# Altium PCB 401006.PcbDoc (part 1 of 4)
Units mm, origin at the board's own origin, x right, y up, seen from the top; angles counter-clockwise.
Board outline 117 x 63.5 mm, 4 copper layers (Top Layer, Mid-Layer 1, Mid-Layer 2, Bottom Layer), stack 1.68 mm thick; 205 components, 151 nets, 838 pads, 1570 vias.
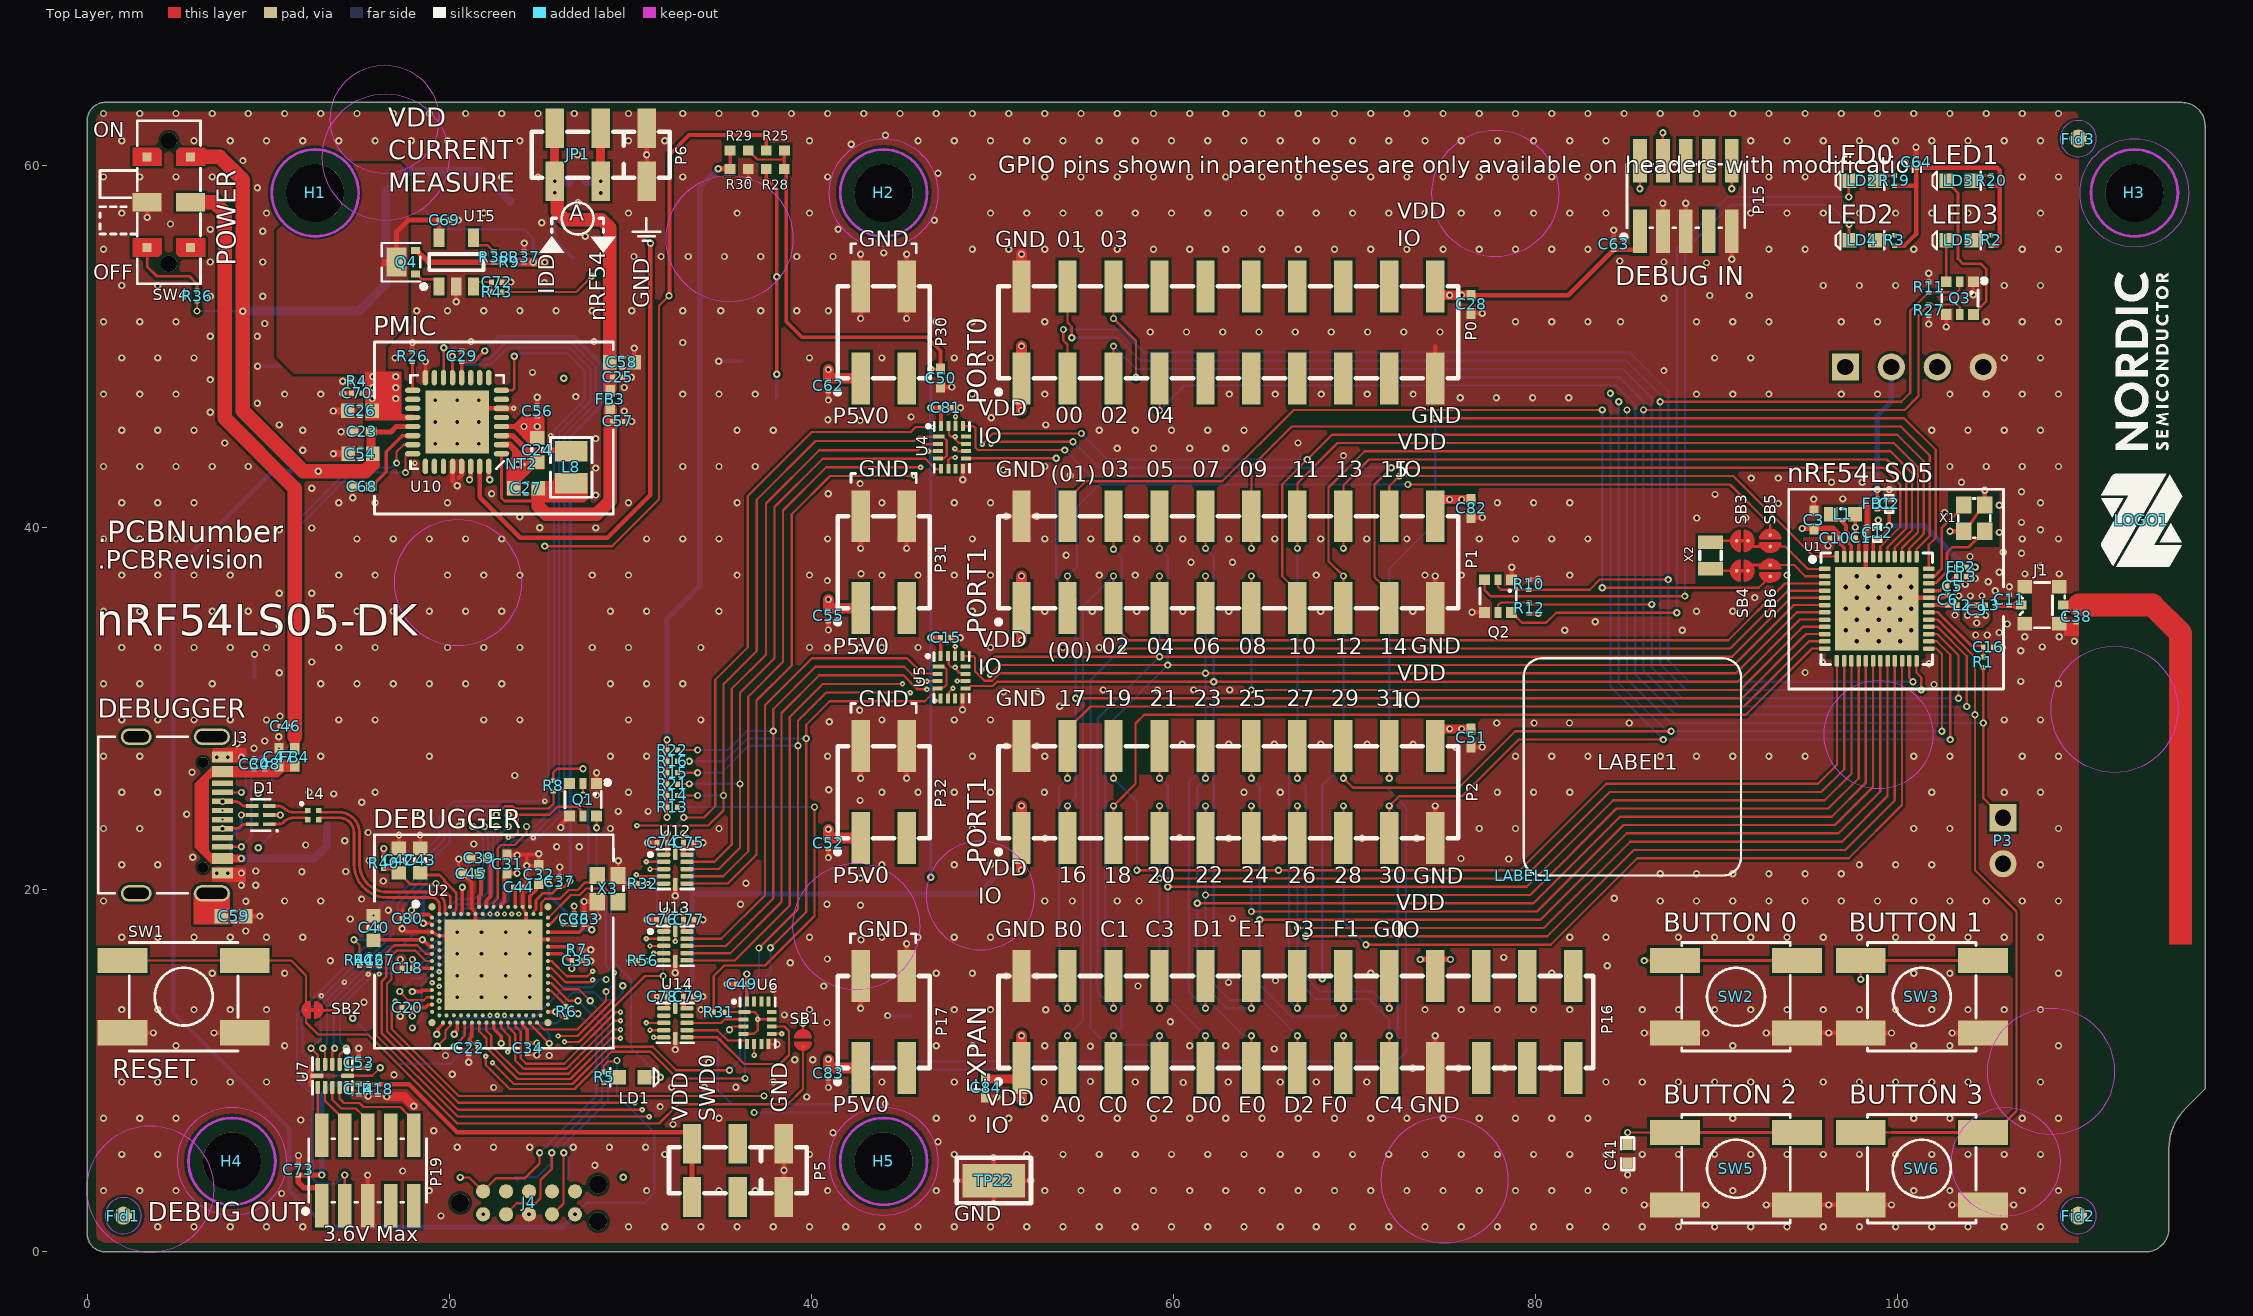
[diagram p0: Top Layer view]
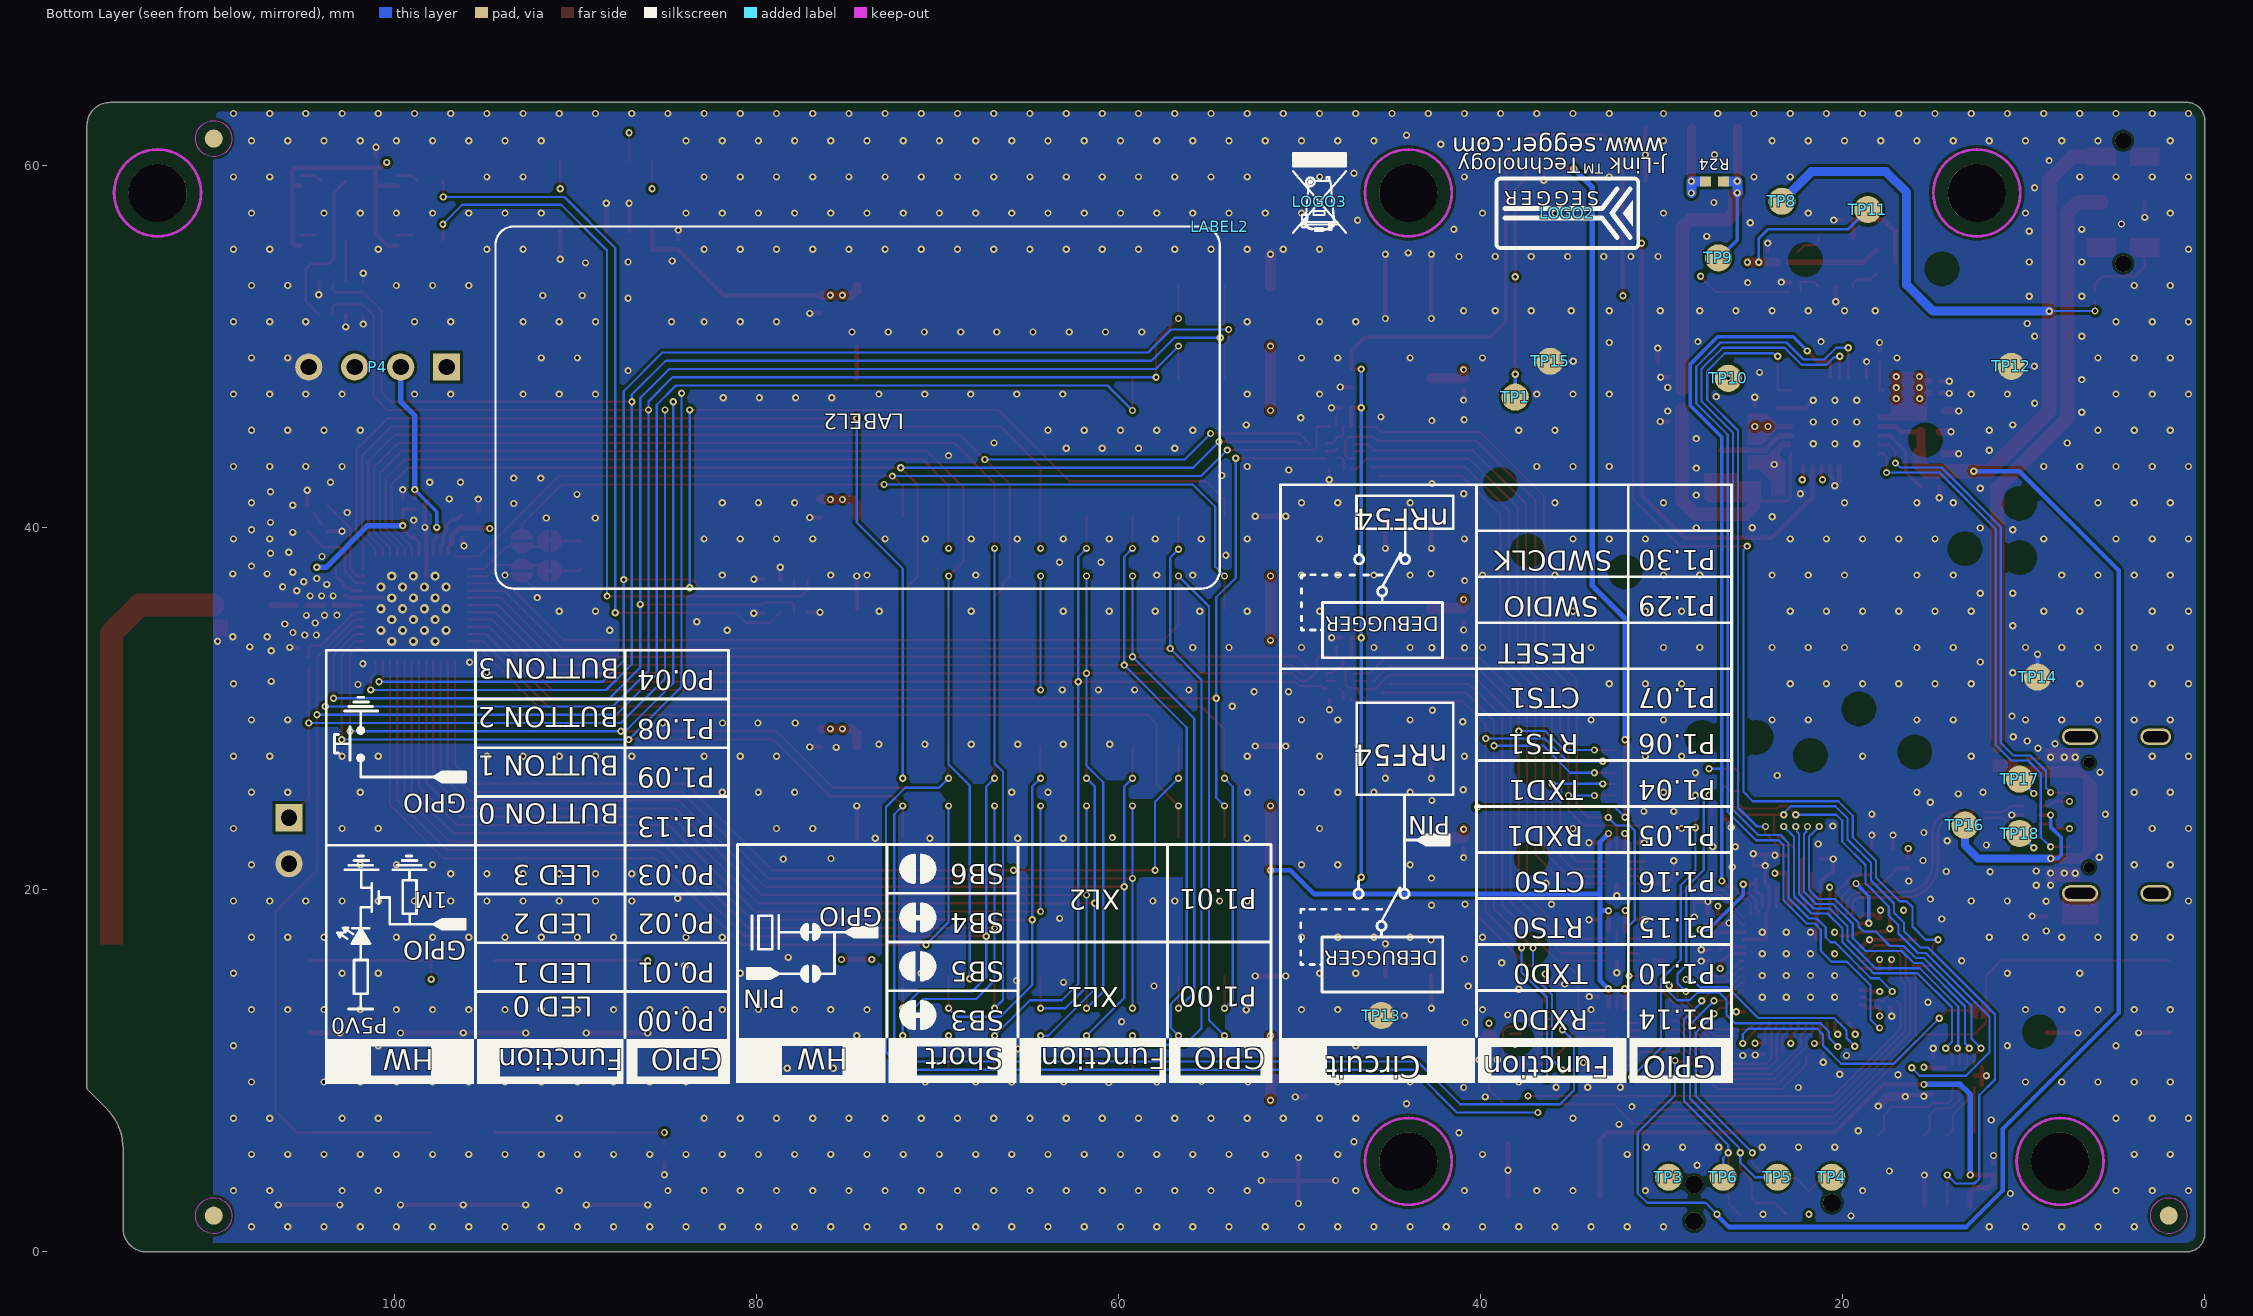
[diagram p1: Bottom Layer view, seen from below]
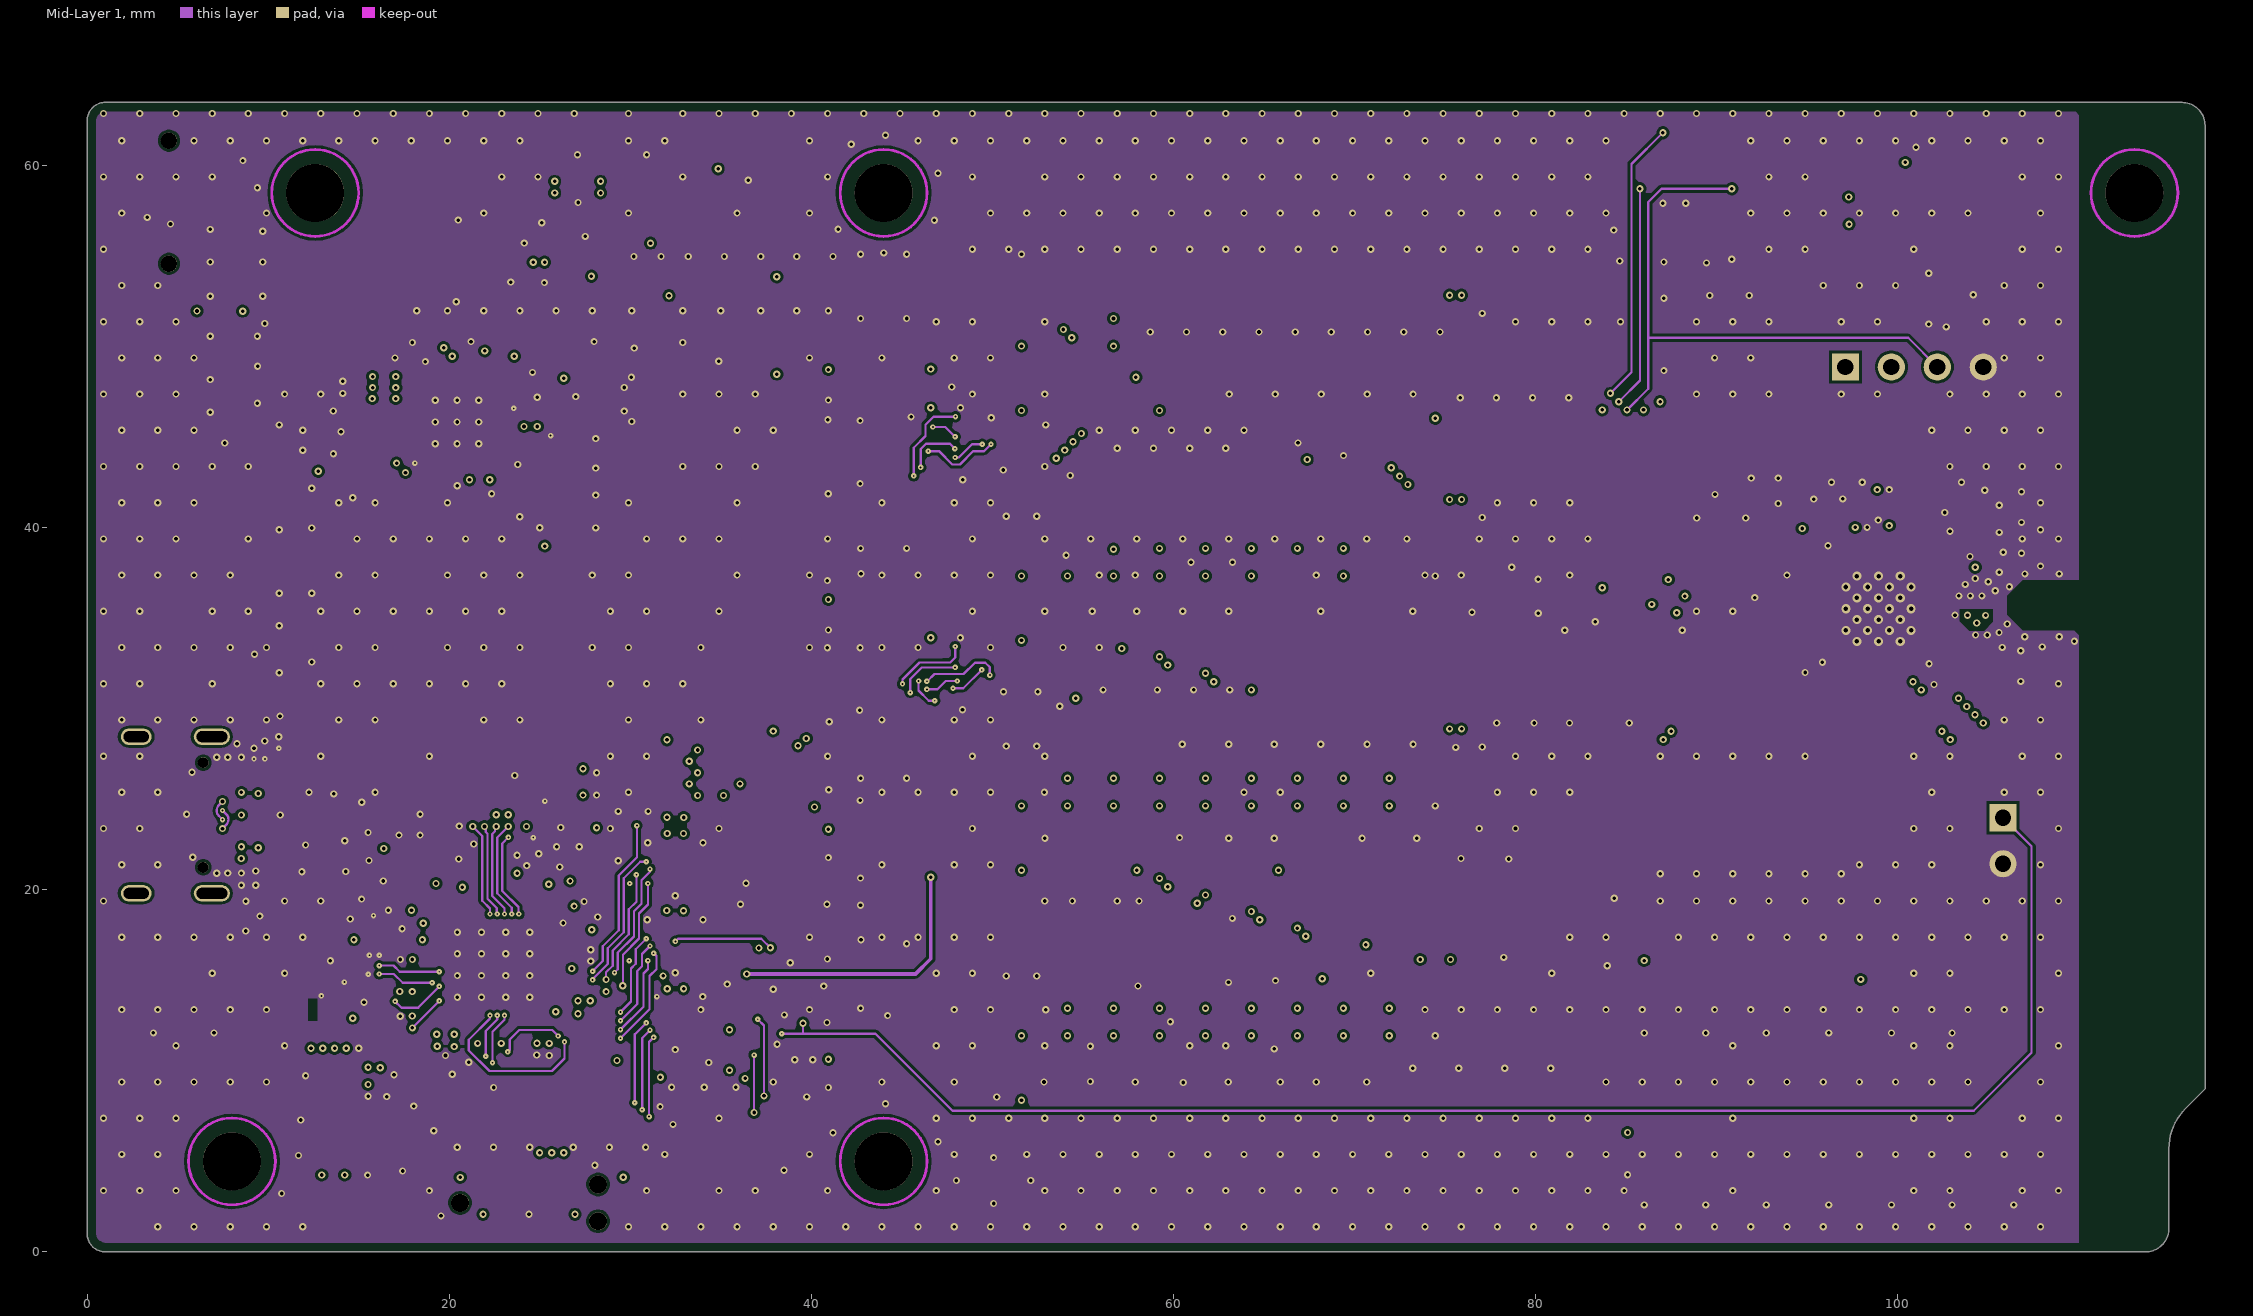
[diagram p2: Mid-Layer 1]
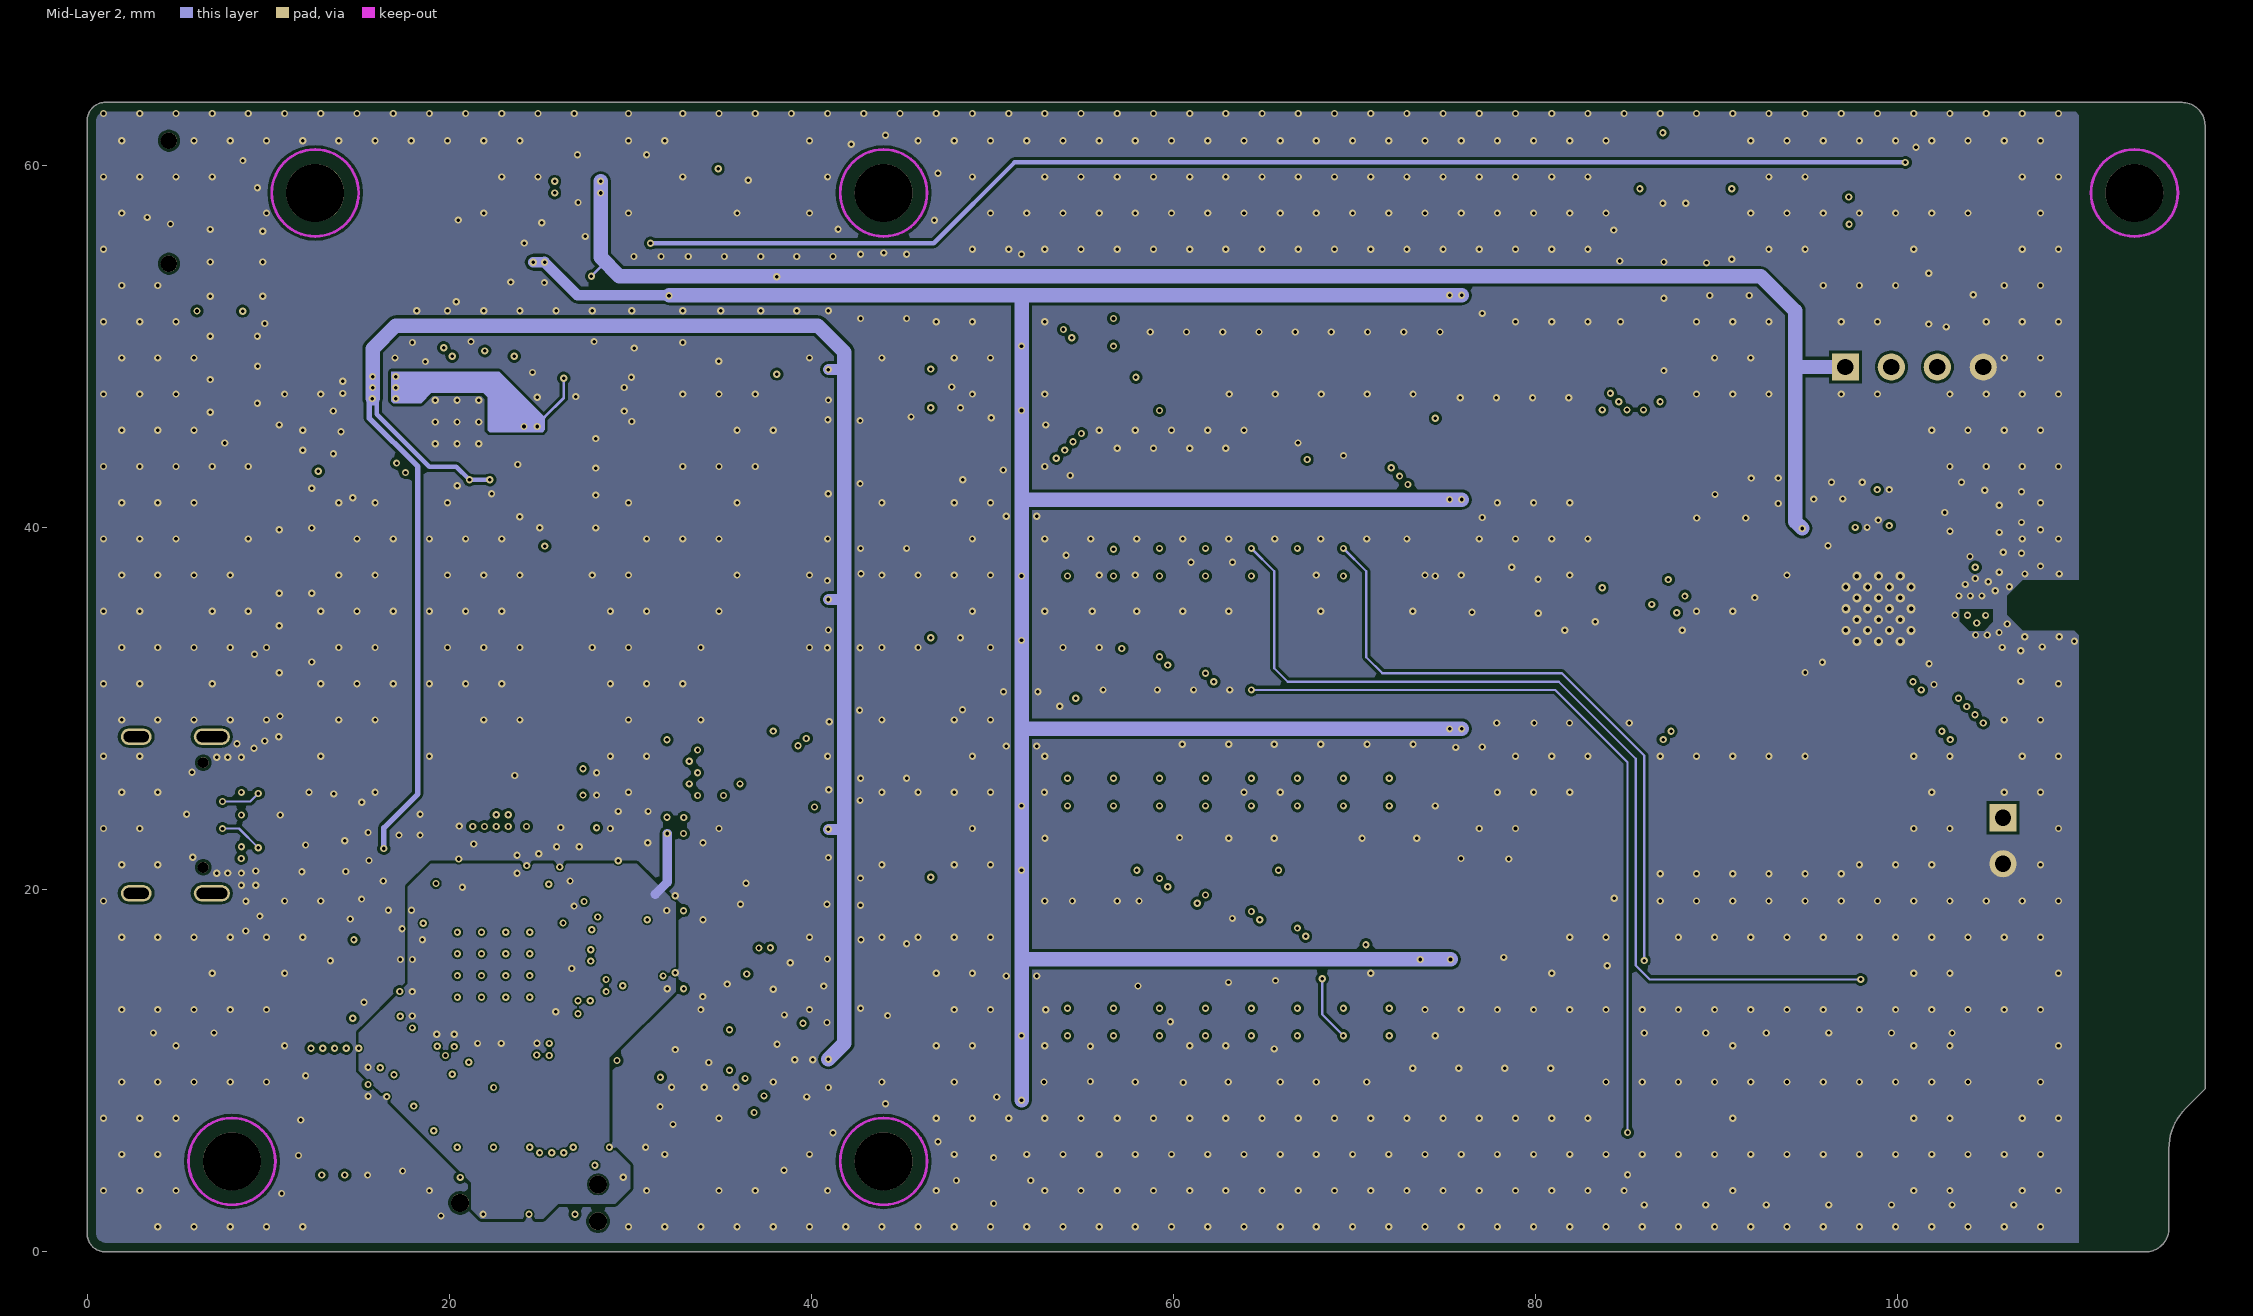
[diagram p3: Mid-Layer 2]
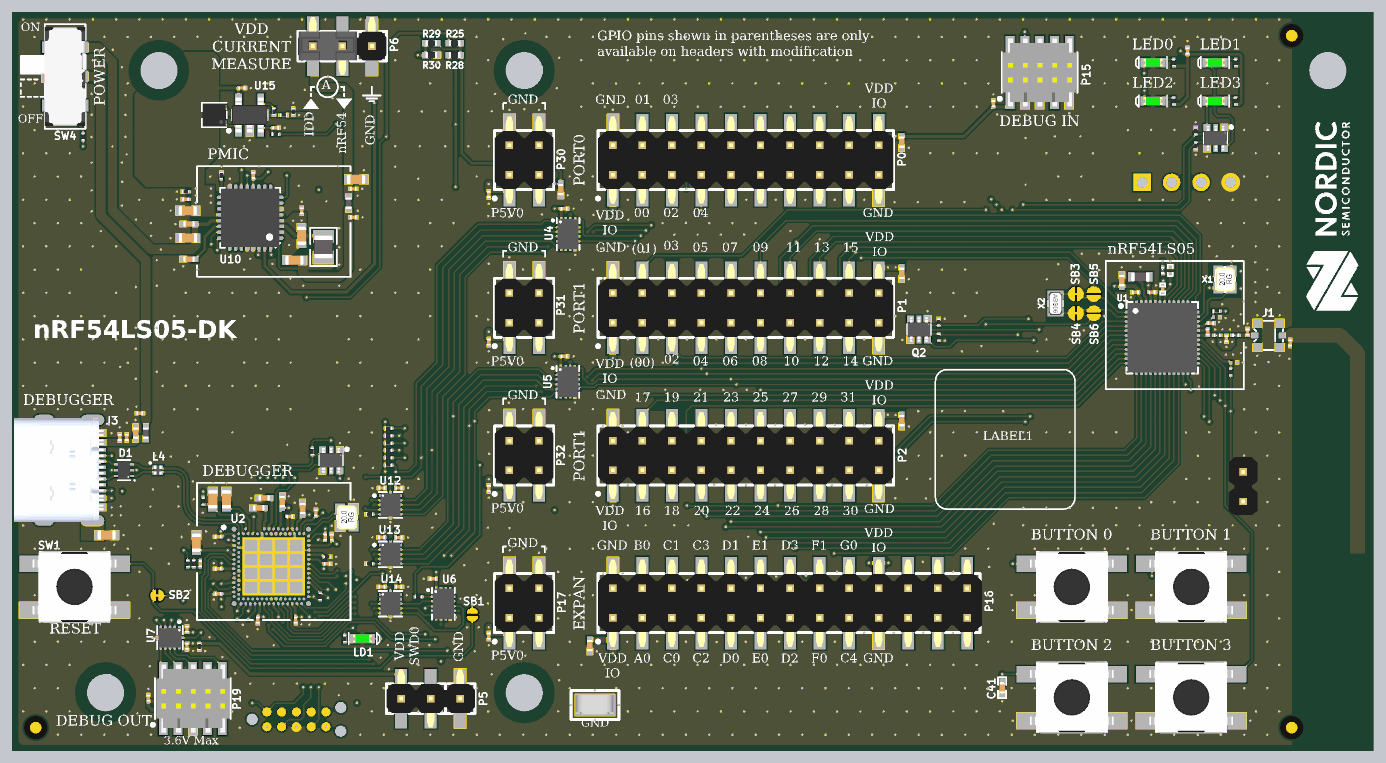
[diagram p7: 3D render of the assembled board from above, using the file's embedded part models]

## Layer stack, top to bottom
Top Solder: solder mask 0.0254, SM-003, Dk 4
Top Layer: signal copper 0.035
Dielectric 1: prepreg 0.07, PP-021, Dk 4.2
Mid-Layer 1: signal copper 0.035
Dielectric 2: core 1.4, Core-042, Dk 4.2
Mid-Layer 2: signal copper 0.035
Dielectric 3: prepreg 0.07, PP-021, Dk 4.2
Bottom Layer: signal copper 0.035
Bottom Solder: solder mask 0.0254, SM-003, Dk 4

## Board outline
1.016,0 cw(c1.016,1.016) 0,1.016 0,62.484 cw(c1.016,62.484) 1.016,63.5 115.734,63.5 cw(c115.734,62.23) 117.004,62.23 117.004,9 115.92,7.916 ccw(c118.132,5.705) 115.004,5.705 115.004,1.295 cw(c113.709,1.295) 113.709,0

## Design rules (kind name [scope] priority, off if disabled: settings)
AssemblyTestPointUsage [All] p1 off:
AssemblyTestpoint [All] p1 off: testpointundercomponent=TRUE minsize=1.016 maxsize=2.54 preferedsize=1.524 minholesize=0 maxholesize=1.016 preferedholesize=0.813 testpointgrid=0.025 usegrid=TRUE gridtolerance=0 allowsidetop=TRUE allowsidebottom=TRUE
BoardOutlineClearance [All] p1: gap=0.508 ignorepadtopadclearanceinfootprint=FALSE except(0: Arc-SplitContinuation Track-SplitContinuation SMDPad-SplitContinuation THPad-SplitContinuation Via-SplitContinuation Fill-SplitContinuation Poly-SplitContinuation Region-SplitContinuation Text-SplitContinuation)
Clearance "Schematic Clearance Constraint_4" [InComponent('H3')] p1: gap=0.254 ignorepadtopadclearanceinfootprint=TRUE except(0: Arc-Hole Track-Hole SMDPad-Hole THPad-Hole Via-Hole Fill-Hole Poly-Hole Region-Hole Text-Hole)
Clearance "Schematic Clearance Constraint_3" [InComponent('H4')] p2: gap=0.254 ignorepadtopadclearanceinfootprint=TRUE except(0: Arc-Hole Track-Hole SMDPad-Hole THPad-Hole Via-Hole Fill-Hole Poly-Hole Region-Hole Text-Hole)
Clearance "Schematic Clearance Constraint_2" [InComponent('H2')] p3: gap=0.254 ignorepadtopadclearanceinfootprint=TRUE except(0: Arc-Hole Track-Hole SMDPad-Hole THPad-Hole Via-Hole Fill-Hole Poly-Hole Region-Hole Text-Hole)
Clearance "Schematic Clearance Constraint_1" [InComponent('H5')] p4: gap=0.254 ignorepadtopadclearanceinfootprint=TRUE except(0: Arc-Hole Track-Hole SMDPad-Hole THPad-Hole Via-Hole Fill-Hole Poly-Hole Region-Hole Text-Hole)
Clearance "Schematic Clearance Constraint" [InComponent('H1')] p5: gap=0.254 ignorepadtopadclearanceinfootprint=TRUE except(0: Arc-Hole Track-Hole SMDPad-Hole THPad-Hole Via-Hole Fill-Hole Poly-Hole Region-Hole Text-Hole)
Clearance ANT_Clearance [InNet('ANT') or InNet('RF') or InNet('NetC9_2') or InNet('NetC6_2')] p6: gap=0.127 ignorepadtopadclearanceinfootprint=FALSE
Clearance Polygon_Clearance [(InNamedPolygon('Mid_Layer1-GND')) or (InNamedPolygon('Bottom_Layer-GND')) or (InNamedPolygon('Mid_Layer2-GND')) or (InNamedPolygon('Top_Layer-GND'))] p7: gap=0.15 ignorepadtopadclearanceinfootprint=FALSE
Clearance Clearance_IMCU [WithinRoom('nRF5340')] p8: gap=0.1 ignorepadtopadclearanceinfootprint=FALSE
Clearance DiffPair_Clearance [InNetClass('IMCU_USB')] p9: gap=0.127 ignorepadtopadclearanceinfootprint=FALSE
Clearance [All] p10: gap=0.1 ignorepadtopadclearanceinfootprint=FALSE
ComponentClearance [All] p1 off: gap=0.254 collisioncheckmode=3 verticalgap=0.254 showdistances=FALSE
DiffPairsRouting [InDifferentialPairClass('All Differential Pairs')] p1: maxlimit=0.15 minlimit=0.127 mostfreqgap=0.15 toplayer_mingap=0.15 toplayer_minwidth=0.15 toplayer_maxwidth=0.155 toplayer_prefwidth=0.153 midlayer1_maxgap=0.127 midlayer1_prefgap=0.127 midlayer1_minwidth=0.082 midlayer1_maxwidth=0.13 midlayer1_prefwidth=0.082 midlayer4_maxgap=0.127 midlayer4_prefgap=0.127 midlayer4_minwidth=0.082 midlayer4_maxwidth=0.13 midlayer4_prefwidth=0.082 bottomlayer_mingap=0.15 bottomlayer_minwidth=0.15 bottomlayer_maxwidth=0.155 bottomlayer_prefwidth=0.153 maxuncoupledlength=10
FabricationTestPointUsage TestPointUsage [All] p1 off: valid=2 allowmultiple=FALSE
FabricationTestpoint Testpoint [All] p1 off: side=2 testpointundercomponent=TRUE minsize=1.016 maxsize=2.54 preferedsize=1.524 minholesize=0 maxholesize=1.016 preferedholesize=0.813 testpointgrid=2.54 allowsidebottom=TRUE usegrid=TRUE gridtolerance=0
Height [All] p1 off: minheight=0 maxheight=25.4 prefheight=12.7
HoleSize [All] p1: absolutevalues=TRUE maxlimit=5 minlimit=0.1 maxpercent=80.000 minpercent=20.000
HoleToHoleClearance [IsThruVia] p1: gap=0.35 allowstackedmicrovias=FALSE
LayerPairs [All] p1 off: enforce=TRUE
MatchedLengths MatchedLengths-Diffpairs [InDifferentialPairClass('All Differential Pairs')] p1: tolerance=1.27 checknetsindiffpair=TRUE checkdiffpairvsdiffpair=FALSE checkxsignals=FALSE checkothers=FALSE
MinimumAnnularRing [All] p1 off: minimumring=0.1
MinimumSolderMaskSliver [All] p1 off: minsoldermaskwidth=0.09
NetAntennae [All] p1 off: netantennaetolerance=0.3
PolygonConnect PolygonConnect_TP [HasFootprint('TP_SMD_D1.5mm') vs InNet('GND')] p1: connectstyle=Direct reliefconductorwidth=0.254 reliefentries=4 polygonreliefangle="90 Angle" airgapwidth=0.254
PolygonConnect PolygonConnect_SMT_Pads [HasFootprint('COAXIAL-SWF') or InComponent('C1','C2','C3','C5','C6','C9','C10','C11','C12','C13','C16','C38') or InComponent('TP22') or InComponent('U9') vs InNet('GND')] p2: connectstyle=Direct reliefconductorwidth=0.254 reliefentries=4 polygonreliefangle="90 Angle" airgapwidth=0.254
PolygonConnect Direct [IsPolygon] p3: connectstyle=Direct reliefconductorwidth=0.254 reliefentries=4 polygonreliefangle="90 Angle" airgapwidth=0.254
PolygonConnect [All] p4: thpad.connectstyle=Relief thpad.reliefconductorwidth=0.254 thpad.reliefentries=4 thpad.polygonreliefangle="90 Angle" thpad.airgapwidth=0.15 smdpad.connectstyle=Relief smdpad.reliefconductorwidth=0.254 smdpad.reliefentries=4 smdpad.polygonreliefangle="90 Angle" smdpad.airgapwidth=0.15 via.connectstyle=Direct via.reliefconductorwidth=0.254 via.reliefentries=4 via.polygonreliefangle="90 Angle" via.airgapwidth=0.254
RoutingVias "Schematic Routing Via Style_4" [InComponent('H3')] p1: holewidth=0 width=0 viastyle="Through Hole" minholewidth=0 minwidth=0 maxholewidth=2 maxwidth=2
RoutingVias "Schematic Routing Via Style_3" [InComponent('H5')] p2: holewidth=0 width=0 viastyle="Through Hole" minholewidth=0 minwidth=0 maxholewidth=2 maxwidth=2
RoutingVias "Schematic Routing Via Style_2" [InComponent('H1')] p3: holewidth=0 width=0 viastyle="Through Hole" minholewidth=0 minwidth=0 maxholewidth=2 maxwidth=2
RoutingVias "Schematic Routing Via Style_1" [InComponent('H2')] p4: holewidth=0 width=0 viastyle="Through Hole" minholewidth=0 minwidth=0 maxholewidth=2 maxwidth=2
RoutingVias "Schematic Routing Via Style" [InComponent('H4')] p5: holewidth=0 width=0 viastyle="Through Hole" minholewidth=0 minwidth=0 maxholewidth=2 maxwidth=2
RoutingVias RoutingVias_Blind [IsBlindVia or IsMicroVia] p6: holewidth=0.711 width=1.27 viastyle="Through Hole" minholewidth=0.711 minwidth=1.27 maxholewidth=0.711 maxwidth=1.27 useviatemplates=TRUE viatemplateguid#1={B6F7EE11-84B8-42C4-BDC0-4B8B407402DD} viatemplatename#1=v30h10m0
RoutingVias RoutingVias_thru [IsThruVia] p7: holewidth=0.305 width=0.61 viastyle="Through Hole" minholewidth=0.305 minwidth=0.61 maxholewidth=0.711 maxwidth=1.27 useviatemplates=TRUE viatemplateguid#1={45043F2C-6C30-44B1-8A5A-A064C5BAA89B} viatemplateguid#2={462064FF-42C7-473E-A651-561C1576AFDF} viatemplateguid#3={462064FF-42C7-473E-A651-561C1576AFDF} viatemplatename#1=v40h20 viatemplatename#2=v50h25m0mx0 viatemplatename#3=v50h25m0mx0
ShortCircuit ShortCircuit_P15_P16 [InComponent('P15') vs InComponent('P16')] p1: allowed=TRUE
ShortCircuit ShortCircuit_PSS [InNet('PVSS1') or InNet('PVSS2') vs InNet('GND')] p2: allowed=TRUE
ShortCircuit [All] p3: allowed=FALSE
SignalStimulus [All] p1: kind=1 level=0 starttime=10.00n stoptime=250.0n periodtime=150.0n
SilkToSilkClearance [All] p1 off: silktosilkclearance=0.254
SilkToSolderMaskClearance SilkscreenOverComponentPads [IsPad] p1 off: minsilkscreentomaskgap=0.254 clearancetoexposedcopper=TRUE
SolderMaskExpansion SolderMaskExpansion_XFDFN40 [HasFootprint('XFDFN40P180X120X40-8M')] p1: expansion=0.02 istentingtop=FALSE
SolderMaskExpansion SolderMaskExpansion_footprints [HasFootprint('UDFN65P200X200X60_HS-6N') or HasFootprint('SON50P300X80-HS-11N') or HasFootprint('US8') or HasFootprint('SON50P300X80_HS-9N') or HasFootprint('BGA25C40P5X5_200X200X50') or HasFootprint('QFN40P180X140X55-10N') or HasFootprint('DX07S016JA1R1500') or HasFootprint('AQFN40P700X700X85_HS-99N') or HasFootprint('Nordic_QFN50P500X500X90-33N') or HasFootprint('QFN12P40_170X200X55L50X20')] p2: expansion=0.03 istentingtop=FALSE
SolderMaskExpansion SolderMaskExpansion_VIA [IsVia] p3: expansion=0.076 istentingtop=TRUE
SolderMaskExpansion [All] p4: expansion=0.05 istentingtop=FALSE
SupplyNets "Schematic Supply Nets" [InNet('VDD:IO')] p1: voltage=0.000
SupplyNets "Schematic Supply Nets_1" [InNet('VBUS')] p2: voltage=0.000
SupplyNets "Schematic Supply Nets_15" [InNet('VDD:SW')] p3: voltage=0.000
SupplyNets "Schematic Supply Nets_14" [InNet('VDD:DBGR')] p4: voltage=0.000
SupplyNets "Schematic Supply Nets_10" [InNet('VDD:SWD0')] p5: voltage=0.000
SupplyNets "Schematic Supply Nets_9" [InNet('VDD:nRF')] p6: voltage=0.000
SupplyNets "Schematic Supply Nets_7" [InNet('VDD:SW_PU')] p7: voltage=0.000
SupplyNets "Schematic Supply Nets_13" [InNet('VDD')] p8: voltage=0.000
SupplyNets "Schematic Supply Nets_12" [InNet('P5V0')] p9: voltage=0.000
SupplyNets "Schematic Supply Nets_11" [InNet('GND')] p10: voltage=0.000
SupplyNets "Schematic Supply Nets_3" [InNet('PVSS1')] p11: voltage=0.000
SupplyNets "Schematic Supply Nets_2" [InNet('VBUSOUT')] p12: voltage=0.000
Width [All] p1: maxlimit=2.5 minlimit=0.125 preferedwidth=0.15
15 further rules are at their usual default settings.

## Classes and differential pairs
component class pca10214_sheet1_connections: SB1 SB2
net class UART1: P1.04/AIN0 P1.05/AIN1 P1.06/AIN2 P1.07/AIN3
net class LEDS: P0.00 P0.01 P0.02 P0.03
net class SWD_nRF54: NRESET P1.29/SWDIO P1.30/SWDCLK
net class UART0: P1.10 P1.14 P1.15 P1.16
net class GPIO_P1: P1.00 P1.01 P1.02 P1.03 P1.04/AIN0 P1.05/AIN1 P1.06/AIN2 P1.07/AIN3 P1.08 P1.09 P1.10 P1.11 P1.12 P1.13 P1.14 P1.15 P1.16 P1.17 P1.18 P1.19 P1.20 P1.21 P1.22 P1.23 P1.24 P1.25 P1.26 P1.27 P1.28 P1.29/SWDIO P1.30/SWDCLK P1.31
net class GPIO_P0: P0.00 P0.01 P0.02 P0.03 P0.04
net class BUTTONS: P0.04 P1.08 P1.09 P1.13
differential pair class DBGR: DBGR DBGR' DBGR''
net class DBGR_USB: DBGR''_N DBGR''_P DBGR'_N DBGR'_P DBGR_N DBGR_P
component class "Power supply": C23 C24 C25 C26 C27 C29 C56 C57 C58 C68 C69 C70 C72 FB3 JP1 L8 NT2 P6 Q4 R4 R9 R24 R26 R37 R38 R43 TP8 TP9 TP10 TP11 TP12 TP13 TP14 TP15 U10 U15
component class "Level shifters and Switches": C14 C15 C49 C50 C53 C74 C75 C76 C77 C78 C79 C81 R8 R13 R14 R15 R16 R18 R21 R22 R25 R28 R29 R30 R31 U4 U5 U6 U7 U12 U13 U14
component class nRF54LS05: C1 C2 C3 C5 C6 C9 C10 C11 C12 C13 C16 C38 C41 FB1 FB2 J1 L1 L2 L3 P3 P4 R1 SB3 SB4 SB5 SB6 TP1 U1 X1 X2
component class Debugger: C18 C20 C22 C31 C32 C33 C34 C35 C36 C37 C39 C40 C42 C43 C44 C45 C67 C80 J4 LD1 Q1 R5 R6 R7 R32 R40 R41 R42 R56 TP3 TP4 TP5 TP6 U2 X3
component class Misc: C64 LD2 LD3 LD4 LD5 Q2 Q3 R2 R3 R10 R11 R12 R19 R20 R27 SW1 SW2 SW3 SW5 SW6
component class Connectors: C28 C30 C46 C47 C48 C51 C52 C54 C55 C59 C62 C63 C73 C82 C83 C84 D1 FB4 J3 L4 P0 P1 P2 P5 P15 P16 P17 P19 P30 P31 P32 R36 SW4 TP16 TP17 TP18 TP22
component class Mechanical: Fid1 Fid2 Fid3 H1 H2 H3 H4 H5 LABEL1 LABEL2 LOGO1 LOGO2 LOGO3
differential pair DBGR'': +DBGR''_P -DBGR''_N
differential pair DBGR: +DBGR_P -DBGR_N
differential pair DBGR': +DBGR'_P -DBGR'_N

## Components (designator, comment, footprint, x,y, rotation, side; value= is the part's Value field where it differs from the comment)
C1 "2.2µF" CAPC0603X03L_C 97.983,39.439 r180 top
C2 "N.C." CAPC0603X03L_C_NC 99.556,41.317 r270 top
C3 "10µF" CAPC1005X04L 95.391,40.428 r270 top
C5 "10nF" CAPC0603X03L_C 103.038,36.779 r180 top
C6 "0.4pF" CAPC0603X03L_C 102.788,36.015 r270 top
C9 "1.5pF" CAPC0603X03L_C 104.388,35.445 r90 top
C10 "100nF" CAPC0603X03L_C 96.559,39.438 r180 top
C11 "1.0pF" CAPC0603X03L_C 106.198,36.016 r270 top
C12 "2.2µF" CAPC0603X03L_C 98.896,39.717 r270 top
C13 "N.C." CAPC0603X03L_C_NC 103.545,37.297 r180 top
C14 "100nF" CAPC0603X03L_C 15.004,8.992 r270 top
C15 "100nF" CAPC0603X03L_C 47.428,33.928 r0 top
C16 "N.C." CAPC0603X03L_C_NC 105.038,33.393 r180 top
C18 "100nF" CAPC0603X03L_C 17.689,15.659 r180 top
C20 "100nF" CAPC0603X03L_C 17.689,13.499 r180 top
C22 "100nF" CAPC0603X03L_C 21.092,11.239 r270 top
C23 "2.2µF" CAPC1005X04L 15.184,45.313 r0 top
C24 "10µF" CAPC1608X06L 24.867,44.296 r90 top
C25 "100nF" CAPC0603X03L_C 29.305,48.321 r180 top
C26 "10µF" CAPC1608X06L 15.082,46.456 r0 top
C27 "10µF" CAPC1608X06L 24.249,42.186 r0 top
C28 "1.0µF" CAPC1005X04L 76.466,52.345 r90 top
C29 "100nF" CAPC0603X03L_C 20.7,49.475 r90 top
C30 "10nF" CAPC0603X03L_C 9.225,26.95 r90 top
C31 "1.0µF" CAPC1005X04L 23.2,21.424 r90 top
C32 "1.0µF" CAPC1005X04L 24.953,20.84 r270 top
C33 "2.2nF" CAPC0603X03L_C 27.459,18.376 r90 top
C34 "100nF" CAPC0603X03L_C 24.343,11.239 r270 top
C35 "100nF" CAPC0603X03L_C 27.068,16.078 r0 top
C36 "100nF" CAPC0603X03L_C 26.909,18.376 r270 top
C37 "100nF" CAPC0603X03L_C 26.096,20.459 r90 top
C38 "1.4pF" CAPC0603X03L_C 109.88,35.08 r90 top
C39 "1.0µF" CAPC1005X04L 21.651,21.754 r0 top
C40 "2.2µF" CAPC1608X06L 15.825,17.9 r90 top
C41 "100nF" CAPC1005X04L 85.105,5.426 r90 top
C42 "4.7µF" CAPC1608X06L 17.231,21.627 r90 top
C43 "4.7µF" CAPC1608X06L 18.4,21.627 r90 top
C44 "100nF" CAPC0603X03L_C 23.835,20.154 r0 top
C45 "1.0µF" CAPC1005X04L 21.194,20.891 r0 top
C46 "100nF" CAPC0603X03L_C 10.95,29.025 r0 top
C47 "1.0µF" CAPC1005X04L 10.6,27.325 r270 top
C48 "100nF" CAPC0603X03L_C 9.825,26.95 r270 top
C49 "100nF" CAPC0603X03L_C 36.165,14.794 r180 top
C50 "1.0µF" CAPC1005X04L 47.15,48.269 r90 top
C51 "1.0µF" CAPC1005X04L 76.466,28.393 r90 top
C52 "100nF" CAPC0603X03L_C 40.956,22.575 r90 top
C53 "100nF" CAPC0603X03L_C 15.004,10.459 r270 top
C54 "4.7µF" CAPC1608X06L 15.1,44.1 r180 top
C55 "100nF" CAPC0603X03L_C 40.956,35.148 r90 top
C56 "100nF" CAPC0603X03L_C 24.867,46.446 r270 top
C57 "100nF" CAPC0603X03L_C 29.305,45.874 r180 top
C58 "4.7µF" CAPC1608X06L 29.55,49.139 r0 top
C59 "10nF" CAPC1608X06L 8.1,18.552 r0 top
C62 "100nF" CAPC0603X03L_C 40.956,47.848 r90 top
C63 "100nF" CAPC0603X03L_C 84.346,55.655 r270 top
C64 "100nF" CAPC0603X03L_C 101.039,60.185 r270 top
C67 "10nF" CAPC0603X03L_C 16.145,16.1 r90 top
C68 "1.0µF" CAPC1005X04L 15.184,42.275 r0 top
C69 "100nF" CAPC0603X03L_C 19.735,57 r0 top
C70 "100nF" CAPC0603X03L_C 14.9,47.425 r0 top
C72 "100nF" CAPC0603X03L_C 22.635,53.575 r0 top
C73 "100nF" CAPC0603X03L_C 11.679,4.531 r270 top
C74 "100nF" CAPC0603X03L_C 31.766,22.604 r180 top
C75 "100nF" CAPC0603X03L_C 33.233,22.604 r0 top
C76 "100nF" CAPC0603X03L_C 31.746,18.354 r180 top
C77 "100nF" CAPC0603X03L_C 33.233,18.344 r0 top
C78 "100nF" CAPC0603X03L_C 31.764,14.104 r180 top
C79 "100nF" CAPC0603X03L_C 33.22,14.104 r0 top
C80 "100nF" CAPC0603X03L_C 17.689,18.401 r180 top
C81 "100nF" CAPC0603X03L_C 47.433,46.628 r0 top
C82 "1.0µF" CAPC1005X04L 76.466,41.068 r90 top
C83 "100nF" CAPC0603X03L_C 40.956,9.875 r90 top
C84 "1.0µF" CAPC1005X04L 49.643,9.056 r90 top
D1 "PRTR5V0U2F,115" SON50P100X50-6N 9.6,24.134 r180 top
FB1 "120R/0.2A" INDC0603X03L_C 98.896,41.317 r270 top
FB2 "0R" RESC0603X03L_C 103.545,37.821 r0 top
FB3 "120R/0.55A" INDC1005X04L 28.905,47.096 r90 top
FB4 "120R/0.55A" INDC1005X04L 11.475,27.325 r90 top
Fid1 "Fiducial mark" Fiducial 2,2 r0 top locked value=N.A.
Fid2 "Fiducial mark" Fiducial 110,2 r0 top locked value=N.A.
Fid3 "Fiducial mark" Fiducial 110,61.5 r0 top locked value=N.A.
H1 "MountingHole_NPTH" MountingHole_3.2_M3 12.604,58.5 r0 top value=MountingHole_3.2_M3
H2 "MountingHole_NPTH" MountingHole_3.2_M3 44.004,58.5 r0 top value=MountingHole_3.2_M3
H3 "MountingHole_NPTH" MountingHole_3.2_M3 113.104,58.5 r0 top value=MountingHole_3.2_M3
H4 "MountingHole_NPTH" MountingHole_3.2_M3 8.004,5 r0 top value=MountingHole_3.2_M3
H5 "MountingHole_NPTH" MountingHole_3.2_M3 44.004,5 r0 top value=MountingHole_3.2_M3
J1 "MM8130-2600" COAXIAL-SWF 108.005,35.73 r90 top locked
J3 "USB-C 2.0" SD-80259-001 5.1,24.134 r270 top locked
J4 "TC2050-IDC" TC2050-IDC-NLFP 24.418,2.709 r0 top locked
JP1 "Shunt 2.54mm" Shunt_2.54mm_Vertical 27.113,60.625 r180 top
L1 "4.7µH" INDC1608X06L 96.991,40.758 r0 top
L2 "2.6nH" INDC0603X03L_C 103.594,35.73 r0 top
L3 "3.3nH" INDC0603X03L_C 105.177,35.731 r0 top
L4 "DLM0NSM900HY2D" CMC0806X05N 12.5,24.134 r270 top locked
L8 "2.2µH" INDC2016X10N 26.749,43.336 r90 top locked
LABEL1 "12x12mm" LabelSilk_12x12 79.365,20.788 r0 top
LABEL2 "20x40mm" LabelSilk_20x40 54.432,56.642 r0 bottom
LD1 "L0603G" LED_0603_G 30.103,9.652 r180 top
LD2 "L0603G" LED_0603_G 98.07,59.181 r0 top locked
LD3 "L0603G" LED_0603_G 103.404,59.181 r0 top locked
LD4 "L0603G" LED_0603_G 98.07,55.879 r0 top locked
LD5 "L0603G" LED_0603_G 103.404,55.879 r0 top locked
LOGO1 "Nordic Logo" NORDIC_LOGO_LYING 113.496,40.415 r90 top
LOGO2 "Segger Logo S" SEGGER_LOGO_S 35.225,57.375 r0 bottom
LOGO3 "WEE Symbol" WEEE_3x4.5mm 48.912,58 r0 bottom
NT2 "Net tie" "2 PIN STARPOINT" 23.983,43.502 r180 top net-tie
P0 "Pin Hdr 2x10" HDR_2x10-SMD 63.054,50.8 r0 top locked
P1 "Pin Hdr 2x10" HDR_2x10-SMD 63.054,38.1 r0 top locked
P2 "Pin Hdr 2x10" HDR_2x10-SMD 63.054,25.4 r0 top locked
P3 "Pin List 1x2" LIST_1x2 105.845,22.713 r270 top locked
P4 "Pin List 1x4" LIST_1x4 100.944,48.884 r0 bottom
P5 "Pin List 1x3" LIST_1x3_SMD 38.5,4.5 r180 top locked
P6 "Pin List 1x3" LIST_1x3_SMD 30.912,60.606 r180 top locked
P15 "Pin Header 2x5, 1.27mm" HDR_2x5-SMD-1.27mm-K 88.324,58.33 r0 top locked
P16 "Pin Hdr 2x13" HDR_2x13-SMD 66.864,12.7 r0 top locked
P17 "Pin Header 2x2 SMD" HDR_2x2-SMD 44.004,12.7 r0 top locked
P19 "Pin Header 2x5, 1.27mm" HDR_2x5-SMD-1.27mm-K 15.504,4.5 r0 top locked
P30 "Pin Header 2x2 SMD" HDR_2x2-SMD 44.004,50.8 r0 top
P31 "Pin Header 2x2 SMD" HDR_2x2-SMD 44.004,38.1 r0 top
P32 "Pin Header 2x2 SMD" HDR_2x2-SMD 44.004,25.4 r0 top locked
Q1 "NX138AKS" TSSOP6 27.401,24.983 r180 top
Q2 "NX138AKS" TSSOP6 77.95,36.231 r180 top
Q3 "NX138AKS" TSSOP6 103.455,52.693 r180 top
Q4 "PBSS4330PA" DFN105P200X65-3N_v2 17.35,54.675 r180 top
R1 "0R" RESC0603X03L_C 104.753,32.581 r270 top
R2 "680R" RESC0603X03L_C 105.182,55.879 r270 top
R3 "680R" RESC0603X03L_C 99.848,55.879 r270 top
R4 "10k" RESC0603X03L_C 14.9,48.091 r0 top
R5 "560R" RESC0603X03L_C 28.56,9.652 r90 top
R6 "100k" RESC0603X03L_C 26.46,13.271 r270 top
R7 "47R" RESC0603X03L_C 27.06,16.687 r0 top
R8 "100k" RESC0603X03L_C 25.76,25.74 r90 top
R9 "0R" RESC0603X03L_C 23.317,54.674 r0 top
R10 "1M0" RESC0603X03L_C 79.652,36.871 r90 top
R11 "1M0" RESC0603X03L_C 101.743,53.296 r90 top
R12 "1M0" RESC0603X03L_C 79.658,35.567 r270 top
R13 "100k" RESC0603X03L_C 32.325,24.575 r0 top
R14 "100k" RESC0603X03L_C 32.325,25.214 r0 top
R15 "100k" RESC0603X03L_C 32.325,26.47 r0 top
R16 "100k" RESC0603X03L_C 32.325,27.098 r0 top
R18 "1M0" RESC0603X03L_C 16.064,8.977 r90 top
R19 "680R" RESC0603X03L_C 99.848,59.181 r270 top
R20 "680R" RESC0603X03L_C 105.182,59.181 r270 top
R21 "100k" RESC0603X03L_C 32.325,25.842 r0 top
R22 "100k" RESC0603X03L_C 32.325,27.726 r0 top
R24 "TBD" RESC1005X04L 27.099,59.141 r180 bottom
R25 "0R" RESC1005X04L 38.025,60.85 r0 top
R26 "47k" RESC0603X03L_C 17.973,49.468 r90 top
R27 "1M0" RESC0603X03L_C 101.743,52.018 r270 top
R28 "0R" RESC1005X04L 38.019,59.83 r0 top
R29 "0R" RESC1005X04L 36.025,60.85 r0 top
R30 "0R" RESC1005X04L 36.025,59.83 r0 top
R31 "100k" RESC0603X03L_C 34.906,13.25 r0 top
R32 "100k" RESC0603X03L_C 30.7,20.35 r180 top
R36 "1k" RESC0603X03L_C 6.075,52.8 r270 top
R37 "10k" RESC0603X03L_C 24.142,54.96 r270 top
R38 "0R" RESC0603X03L_C 22.485,54.96 r270 top
R40 "2R2" RESC0603X03L_C 16.394,21.469 r90 top
R41 "10k" RESC0603X03L_C 15.053,16.099 r90 top
R42 "10k" RESC0603X03L_C 15.6,16.099 r270 top
R43 "33k" RESC0603X03L_C 22.635,53.025 r180 top
R56 "100k" RESC0603X03L_C 30.7,16.09 r180 top
SB1 "Solderbridge" Solderbridge 39.55,11.7 r270 top
SB2 "Solderbridge" Solderbridge_Shorted 12.45,13.364 r0 top net-tie
SB3 "Solderbridge" Solderbridge_SHORTED_0.4 91.442,39.28 r180 top net-tie
SB4 "Solderbridge" Solderbridge_SHORTED_0.4 91.442,37.629 r180 top net-tie
SB5 "Solderbridge" Solderbridge_0.4#1 92.983,39.28 r90 top
SB6 "Solderbridge" Solderbridge_0.4#2 92.983,37.629 r270 top
SW1 "PB SW" Switch-PB-6.2x6.3mm-SMD 5.338,14.097 r180 top
SW2 "PB SW" Switch-PB-6.2x6.3mm-SMD 91.096,14.094 r180 top
SW3 "PB SW" Switch-PB-6.2x6.3mm-SMD 101.357,14.094 r180 top
SW4 "Switch" JS102011JAQN 4.521,57.988 r270 top locked
SW5 "PB SW" Switch-PB-6.2x6.3mm-SMD 91.096,4.594 r180 top
SW6 "PB SW" Switch-PB-6.2x6.3mm-SMD 101.357,4.594 r180 top
TP1 "Ø1.5mm,SMD" TP_SMD_D1.5mm#1 38.104,47.219 r180 bottom
TP3 "Ø1.5mm,SMD" TP_SMD_D1.5mm#2 29.62,4.115 r180 bottom locked
TP4 "Ø1.5mm,SMD" TP_SMD_D1.5mm#2 20.616,4.115 r180 bottom locked
TP5 "Ø1.5mm,SMD" TP_SMD_D1.5mm#2 23.616,4.115 r180 bottom locked
TP6 "Ø1.5mm,SMD" TP_SMD_D1.5mm#2 26.616,4.115 r180 bottom locked
TP8 "Ø1.5mm,SMD" TP_SMD_D1.5mm#1 23.372,58.039 r270 bottom locked
TP9 "Ø1.5mm,SMD" TP_SMD_D1.5mm#1 26.877,54.915 r270 bottom locked
TP10 "Ø1.5mm,SMD" TP_SMD_D1.5mm#1 26.334,48.26 r180 bottom locked
TP11 "Ø1.5mm,SMD" TP_SMD_D1.5mm#1 18.622,57.582 r90 bottom locked
TP12 "Ø1.5mm,SMD" TP_SMD_D1.5mm#1 10.693,48.92 r90 bottom locked
TP13 "Ø1.5mm,SMD" TP_SMD_D1.5mm#1 45.496,13.056 r90 bottom locked
TP14 "Ø1.5mm,SMD" TP_SMD_D1.5mm#1 9.25,31.75 r90 bottom locked
TP15 "Ø1.5mm,SMD" TP_SMD_D1.5mm#1 36.174,49.2 r90 bottom locked
TP16 "Ø1.5mm,SMD" TP_SMD_D1.5mm#1 13.263,23.571 r180 bottom locked
TP17 "Ø1.5mm,SMD" TP_SMD_D1.5mm#1 10.24,26.115 r180 bottom locked
TP18 "Ø1.5mm,SMD" TP_SMD_D1.5mm#1 10.24,23.113 r180 bottom locked
TP22 "TP" S1751 50.082,3.941 r0 top
U1 "nRF54LS05B-QFAA" QFN49P40_600x600x90L40x20T460N 98.868,35.53 r0 top
U2 "nRF5340-QKAA" AQFN40P700X700X85_HS-99N 22.26,15.864 r0 top locked
U4 "TMUX1511" XQFN40P180X260X50-16N 47.778,44.437 r0 top locked
U5 "TMUX1511" XQFN40P180X260X50-16N 47.76,31.736 r0 top
U6 "TMUX1511" XQFN40P180X260X50-16N 37.05,12.65 r0 top
U7 "TXB0104" QFN12P40_170X200X55L50X20 13.55,9.725 r270 top
U10 "nPM1300-QEAA" Nordic_QFN50P500X500X90-33N 20.442,45.846 r180 top locked
U12 "TXB0104" QFN12P40_170X200X55L50X20 32.5,21.15 r0 top
U13 "TXB0104" QFN12P40_170X200X55L50X20 32.5,16.9 r0 top
U14 "TXB0104" QFN12P40_170X200X55L50X20 32.5,12.65 r0 top
U15 "TLV271" SOT95P280X145-5N 20.4,54.675 r90 top
X1 "32MHz" BT-XTAL_2016 104.255,40.534 r90 top
X2 "32.768kHz" XTAL_2012 89.689,38.467 r270 top
X3 "32MHz" BT-XTAL_2016 28.756,20.069 r90 top

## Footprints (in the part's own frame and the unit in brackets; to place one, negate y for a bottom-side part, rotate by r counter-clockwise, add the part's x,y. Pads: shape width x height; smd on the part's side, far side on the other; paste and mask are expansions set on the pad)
"2 PIN STARPOINT" [mil]
  round 6 smd paste-196.85 mask-196.85: 1(8,0) 2(-8,0)
  Top Layer region: -8,-3 8,-3 8,3 -8,3
AQFN40P700X700X85_HS-99N [mm] "AQFN, 98-Leads, Body 7.00x7.00mm, Pitch 0.40mm, Thermal Pad 5.4x5.0mm, IPC Medium Density"
  rect 5.4x5 smd paste-5: 104(0.2,0)
  round 0.4 smd paste+0.012: A1(-3.2,3.2) A31(3.2,3.2) AL1(-3.2,-3.2) AL31(3.2,-3.2)
  round 0.225 smd paste+0.012: A5(-2.2,3.2) A13(-0.6,3.2) A15(-0.2,3.2) A17(0.2,3.2) A19(0.6,3.2) A21(1,3.2) A23(1.4,3.2) A25(1.8,3.2) A27(2.2,3.2) AA1(-3.2,-1) AA31(3.2,-1) AB2(-2.8,-1.2) AC1(-3.2,-1.4) AC31(3.2,-1.4) AD2(-2.8,-1.6) AE1(-3.2,-1.8) AE31(3.2,-1.8) AF2(-2.8,-2) AG1(-3.2,-2.2) AG31(3.2,-2.2) AH2(-2.8,-2.4) AJ1(-3.2,-2.6) AJ31(3.2,-2.6) AK2(-2.8,-2.8) AK4(-2.4,-2.8) AK6(-2,-2.8) AK8(-1.6,-2.8) AK10(-1.2,-2.8) AK12(-0.8,-2.8) AK14(-0.4,-2.8) AK16(0,-2.8) AK18(0.4,-2.8) AK20(0.8,-2.8) AK22(1.2,-2.8) AK24(1.6,-2.8) AK26(2,-2.8) AK28(2.4,-2.8) AK30(2.8,-2.8) AL3(-2.6,-3.2) AL5(-2.2,-3.2) AL7(-1.8,-3.2) AL9(-1.4,-3.2) AL11(-1,-3.2) AL13(-0.6,-3.2) AL15(-0.2,-3.2) AL17(0.2,-3.2) AL19(0.6,-3.2) AL21(1,-3.2) AL23(1.4,-3.2) AL25(1.8,-3.2) AL27(2.2,-3.2) AL29(2.6,-3.2) B2(-2.8,2.8) B4(-2.4,2.8) B6(-2,2.8) B8(-1.6,2.8) B10(-1.2,2.8) B12(-0.8,2.8) B14(-0.4,2.8) B16(0,2.8) B18(0.4,2.8) B20(0.8,2.8) B22(1.2,2.8) B24(1.6,2.8) B26(2,2.8) B28(2.4,2.8) B30(2.8,2.8) C1(-3.2,2.6) C31(3.2,2.6) D2(-2.8,2.4) E1(-3.2,2.2) E31(3.2,2.2) F2(-2.8,2) G1(-3.2,1.8) G31(3.2,1.8) H2(-2.8,1.6) J1(-3.2,1.4) J31(3.2,1.4) K2(-2.8,1.2) L1(-3.2,1) L31(3.2,1) M2(-2.8,0.8) N1(-3.2,0.6) N31(3.2,0.6) P2(-2.8,0.4) R1(-3.2,0.2) R31(3.2,0.2) T2(-2.8,0) U1(-3.2,-0.2) U31(3.2,-0.2) V2(-2.8,-0.4) W1(-3.2,-0.6) W31(3.2,-0.6) Y2(-2.8,-0.8)
  rrect15% 1.1x1 on Top Paste: ""(-1.75,-1.8) ""(-1.75,-0.6) ""(-1.75,0.6) ""(-1.75,1.8) ""(-0.45,-1.8) ""(-0.45,-0.6) ""(-0.45,0.6) ""(-0.45,1.8) ""(0.85,-1.8) ""(0.85,-0.6) ""(0.85,0.6) ""(0.85,1.8) ""(2.15,-1.8) ""(2.15,-0.6) ""(2.15,0.6) ""(2.15,1.8)
  silkscreen extent -4.22,3.23 -3.97,3.47, body extent -3.5,-3.5 3.5,3.5, height 0.85
BT-XTAL_2016 [mm] "Crystal 2.0 x 1.6 mm"
  rect 0.95x0.85 smd: 1(-0.725,-0.575) 2(0.725,-0.575) 3(0.725,0.575) 4(-0.725,0.575)
  silkscreen extent -1.08,-0.88 1.08,0.88, body extent -1.05,-0.85 1.05,0.85, height 0.56
CAPC0603X03L_C [mm] "Chip Capacitor, 2-Leads, Body 0.6x0.3mm, IPC High Density"
  rect 0.27x0.3 smd mask+0.05: 1(-0.285,0) 2(0.285,0)
  body extent -0.3,-0.15 0.3,0.15, height 0.3
CAPC0603X03L_C_NC [mm] "Chip Capacitor, 2-Leads, Body 0.6x0.3mm, IPC High Density"
  rect 0.27x0.3 smd mask+0.05: 1(-0.285,0) 2(0.285,0)
  silkscreen extent -0.49,-0.22 0.49,0.22
CAPC1005X04L [mm] "Chip Capacitor, 2-Leads, Body 1.0x0.5mm, IPC High Density"
  rect 0.6x0.5 smd: 1(-0.5,0) 2(0.5,0)
  body extent -0.5,-0.25 0.5,0.25, height 0.5
CAPC1608X06L [mm] "Chip Capacitor, 2-Leads, Body 1.6x0.8mm, IPC High Density"
  rect 0.75x0.8 smd: 1(-0.675,0) 2(0.675,0)
  silkscreen extent -0.1,-0.3 0.1,0.3, body extent -0.8,-0.4 0.8,0.4, height 0.8
CMC0806X05N [mm]
  rect 0.3x0.3 smd mask+0.05: 1(-0.25,-0.3) 2(0.25,-0.3) 3(0.25,0.3) 4(-0.25,0.3)
  silkscreen extent -0.67,-0.7 -0.58,-0.6, body extent -0.42,-0.32 0.43,0.33, height 0.52
COAXIAL-SWF [mm]
  rect 0.5x0.58 smd: 1(0,1.16) 3(0,-1.16)
  rect 0.75x0.8 smd: 2(-1.025,-0.95) 2(-1.025,0.95) 2(1.025,-0.95) 2(1.025,0.95)
  Top Layer pour cut-out: 0.65,-0.55 -0.65,-0.55 -0.65,-1.35 0.65,-1.35
  Top Layer pour cut-out: -0.65,0.55 0.65,0.55 0.65,1.35 -0.65,1.35
  silkscreen extent -1.25,-1.25 1.25,1.23, body extent -1.26,-1.3 1.26,1.3, height 1.55
DFN105P200X65-3N_v2 [mm] "DFN, 3-Leads, Body 2.00x2.00mm, Pitch 1.05mm, IPC Medium Density"
  rect 0.5x0.4 smd: 1(-0.8,0.65) 2(-0.8,-0.65)
  rect 1.1x1.6 smd: 3(0.25,0)
  Top Layer region: 0.65,-0.2 1.05,-0.2 1.05,0.2 0.65,0.2
  silkscreen extent -1.2,-1.06 1.06,1.36, body extent -1,-1 1,1, height 0.65
Fiducial [mm] "Fiducial Mark"
  round 1 smd paste-2539.97 mask+0.5: 0(0,0)
  round 1 smd far side paste-2539.97 mask+0.5: 0(0,0)
  Top Layer keep-out circle w0.01: c0,0 r1
  Bottom Layer keep-out circle w0.01: c0,0 r1
HDR_2x2-SMD [mil] "Board-Board Conn, Header, 4-way, 2-row"
  rect 40x113 smd: 1(-50,-100) 2(-50,100) 3(50,-100) 4(50,100)
  silkscreen extent -105,-135 100,100, body extent -100,-148 100,148, height 382
HDR_2x5-SMD-1.27mm-K [mm] "SMT MICRO HEADER, (1,27) .050\" Keying Shroud"
  rect 0.76x2.4 smd: 1(-2.54,-1.95) 2(-2.54,1.95) 3(-1.27,-1.95) 4(-1.27,1.95) 5(0,-1.95) 6(0,1.95) 7(1.27,-1.95) 8(1.27,1.95) 9(2.54,-1.95) 10(2.54,1.95)
  silkscreen extent -3.56,-2.38 3.25,1.75, body extent -3.14,-2.92 3.14,2.92, height 6.11
HDR_2x10-SMD [mil] "Board-Board Conn, Header, 20-way, 2-row"
  rect 40x113 smd: 1(-450,-100) 2(-450,100) 3(-350,-100) 4(-350,100) 5(-250,-100) 6(-250,100) 7(-150,-100) 8(-150,100) 9(-50,-100) 10(-50,100) 11(50,-100) 12(50,100) 13(150,-100) 14(150,100) 15(250,-100) 16(250,100) 17(350,-100) 18(350,100) 19(450,-100) 20(450,100)
  silkscreen extent -505,-135 500,100, body extent -500,-148 500,148, height 382
HDR_2x13-SMD [mil] "Board-Board Conn, Header, 26-way, 2-row"
  rect 40x113 smd: 1(-600,-100) 2(-600,100) 3(-500,-100) 4(-500,100) 5(-400,-100) 6(-400,100) 7(-300,-100) 8(-300,100) 9(-200,-100) 10(-200,100) 11(-100,-100) 12(-100,100) 13(0,-100) 14(0,100) 15(100,-100) 16(100,100) 17(200,-100) 18(200,100) 19(300,-100) 20(300,100) 21(400,-100) 22(400,100) 23(500,-100) 24(500,100) 25(600,-100) 26(600,100)
  silkscreen extent -655,-135 643,100, body extent -650,-148 650,148, height 384
INDC0603X03L_C [mm] "Chip Inductor, 2-Leads, Body 0.6x0.3mm, IPC High Density"
  rect 0.27x0.3 smd: 1(-0.285,0) 2(0.285,0)
  body extent -0.3,-0.15 0.3,0.15, height 0.3
INDC1005X04L [mm] "Chip Inductor, 2-Leads, Body 1.0x0.5mm, IPC High Density"
  rect 0.65x0.5 smd: 1(-0.475,0) 2(0.475,0)
  body extent -0.5,-0.25 0.5,0.25, height 0.5
INDC1608X06L [mm] "Chip Inductor, 2-Leads, Body 1.6x0.8mm, IPC High Density"
  rect 0.75x0.8 smd: 1(-0.675,0) 2(0.675,0)
  silkscreen extent -0.1,-0.3 0.1,0.3, body extent -0.8,-0.4 0.8,0.4, height 0.8
INDC2016X10N [mm] "Chip Inductor, 2-Leads, Body 2.00x1.60mm, IPC Medium Density"
  rect 1.13x1.82 smd: 1(-0.885,0) 2(0.885,0)
  silkscreen extent -1.65,-1.14 1.65,1.14, body extent -1,-0.8 1,0.8, height 1
JS102011JAQN [mm] "Slide Switches - DPDT, SMD, ON-ON"
  round 0.9 hole 0.9 unplated mask+0: 0(-3.4,0) 0(3.4,0)
  rect 0.5x0.5 smd: 1(-2.5,-1.2) 3(2.5,-1.2) 4(-2.5,1.2) 6(2.5,1.2)
  rect 1x1.6 smd: 2(0,-1.2) 5(0,1.2)
  Top Layer region: 3,-0.562 2.838,-0.4 2,-0.4 2,-2 3,-2
  Top Layer region: 3,0.562 2.838,0.4 2,0.4 2,2 3,2
  Top Layer region: -3,-0.562 -2.838,-0.4 -2,-0.4 -2,-2 -3,-2
  Top Layer region: -3,0.562 -2.838,0.4 -2,0.4 -2,2 -3,2
  silkscreen extent -4.5,-3.8 4.5,1.75, body extent -4.25,-3.75 4.25,1.75, height 3.5
LabelSilk_12x12 [mm] "PCA version label, stick-on, 12x12mm"
  silkscreen extent 0,0 12,12, body extent 0,0 12,12, height 0.05
LabelSilk_20x40 [mm] "Early Access sticker 20x40mm"
  silkscreen extent 0,0 40,20
LED_0603_G [mil] "SMD Super Bright LED, GREEN"
  rect 30x32 smd: 1(-27.5,0) 2(27.5,0)
  silkscreen extent -58,-20 48,20, body extent -32,-16 32,16, height 24
LIST_1x2 [mm] "Pin List, 2.54mm through hole"
  rect 1.5x1.5 hole 0.9: 1(-1.27,0)
  round 1.5 hole 0.9: 2(1.27,0)
  body extent -2.54,-1.27 2.44,1.23, height 8.2
LIST_1x3_SMD [mm] "Pin List, 2.54mm, SMD"
  rect 1.02x2.19 smd: 1(0,1.465) 1(0,-1.465) 2(2.54,-1.465) 2(2.54,1.465) 3(5.08,-1.465) 3(5.08,1.465)
  silkscreen extent -1.27,-1.27 6.35,1.27, body extent -1.27,-2.5 6.35,2.5, height 9.82
LIST_1x4 [mm] "Pin List, 2.54mm through hole"
  rect 1.5x1.5 hole 0.9: 1(-3.81,0)
  round 1.5 hole 0.9: 2(-1.27,0) 3(1.27,0) 4(3.81,0)
MountingHole_3.2_M3 [mm] "Mounting hole, 3.2mm, M3,no annular"
  round 3.2 hole 3.2 unplated mask+0: ""(0,0)
NORDIC_LOGO_LYING [mm]
  silkscreen extent -2.57,-2.24 13.7,2.24
Nordic_QFN50P500X500X90-33N [mm] "QFN32 5x5x0.85mm, 0.5mm pitch - Medium Density"
  oval 0.85x0.3 smd: 1(-2.45,1.75) 2(-2.45,1.25) 3(-2.45,0.75) 4(-2.45,0.25) 5(-2.45,-0.25) 6(-2.45,-0.75) 7(-2.45,-1.25) 8(-2.45,-1.75) 17(2.45,-1.75) 18(2.45,-1.25) 19(2.45,-0.75) 20(2.45,-0.25) 21(2.45,0.25) 22(2.45,0.75) 23(2.45,1.25) 24(2.45,1.75)
  oval 0.3x0.85 smd: 9(-1.75,-2.45) 10(-1.25,-2.45) 11(-0.75,-2.45) 12(-0.25,-2.45) 13(0.25,-2.45) 14(0.75,-2.45) 15(1.25,-2.45) 16(1.75,-2.45) 25(1.75,2.45) 26(1.25,2.45) 27(0.75,2.45) 28(0.25,2.45) 29(-0.25,2.45) 30(-0.75,2.45) 31(-1.25,2.45) 32(-1.75,2.45)
  rect 3.5x3.5 smd: 33(0,0)
  silkscreen extent -2.57,-2.57 2.57,2.57, body extent -2.5,-2.5 2.5,2.5, height 0.9
QFN12P40_170X200X55L50X20 [mm] "QFN, 12-Leads, Body 2,1x1,8mm (max), Pitch 0,40mm, IPC Low Density"
  rrect50% 0.72x0.25 smd: 1(-0.64,0.8) 2(-0.64,0.4) 3(-0.64,0) 4(-0.64,-0.4) 5(-0.64,-0.8) 7(0.64,-0.8) 8(0.64,-0.4) 9(0.64,0) 10(0.64,0.4) 11(0.64,0.8)
  rrect50% 0.25x0.72 smd: 6(0,-0.85) 12(0,0.85)
  silkscreen extent -1.47,-1.1 1.01,1.1, body extent -0.85,-1 0.85,1, height 0.55
QFN49P40_600x600x90L40x20T460N [mm] "QFN, 48-Leads, Body 6.00x6.00mm, Pitch 0.40mm, Thermal Pad 4.60x4.60mm, IPC Nominal Density"
  rrect50% 0.64x0.25 smd mask+0.03: 1(-2.88,2.2) 2(-2.88,1.8) 3(-2.88,1.4) 4(-2.88,1) 5(-2.88,0.6) 6(-2.88,0.2) 7(-2.88,-0.2) 8(-2.88,-0.6) 9(-2.88,-1) 10(-2.88,-1.4) 11(-2.88,-1.8) 12(-2.88,-2.2) 25(2.88,-2.2) 26(2.88,-1.8) 27(2.88,-1.4) 28(2.88,-1) 29(2.88,-0.6) 30(2.88,-0.2) 31(2.88,0.2) 32(2.88,0.6) 33(2.88,1) 34(2.88,1.4) 35(2.88,1.8) 36(2.88,2.2)
  rrect50% 0.25x0.64 smd mask+0.03: 13(-2.2,-2.88) 14(-1.8,-2.88) 15(-1.4,-2.88) 16(-1,-2.88) 17(-0.6,-2.88) 18(-0.2,-2.88) 19(0.2,-2.88) 20(0.6,-2.88) 21(1,-2.88) 22(1.4,-2.88) 23(1.8,-2.88) 24(2.2,-2.88) 37(2.2,2.88) 38(1.8,2.88) 39(1.4,2.88) 40(1,2.88) 41(0.6,2.88) 42(0.2,2.88) 43(-0.2,2.88) 44(-0.6,2.88) 45(-1,2.88) 46(-1.4,2.88) 47(-1.8,2.88) 48(-2.2,2.88)
  rect 4.6x4.6 smd mask+0.04: 49(0,0)
  silkscreen extent -3.67,-3.08 3.08,3.08, body extent -3,-3 3,3, height 0.9
RESC0603X03L_C [mm] "Chip Resistor, 2-Leads, Body 0.6x0.3mm, IPC High Density"
  rect 0.27x0.3 smd: 1(-0.285,0) 2(0.285,0)
  body extent -0.3,-0.15 0.3,0.15, height 0.23
RESC1005X04L [mm] "Chip Resistor, 2-Leads, Body 1.0x0.5mm, IPC High Density"
  rect 0.6x0.55 smd mask+0.05: 1(-0.5,0) 2(0.5,0)
  body extent -0.5,-0.25 0.5,0.25, height 0.3
S1751 [mm]
  rect 3.45x1.85 smd: 1(0,0)
  silkscreen extent -2.04,-1.25 2.06,1.25, body extent -1.67,-0.8 1.58,0.85, height 2.05
SD-80259-001 [mm] "USB TYPE C RECEPTACLE, 16 PIN"
  round 0.6 hole 0.6 unplated: 0(-2.89,1.315) 0(2.89,1.315)
  rect 0.6x1.14 smd: A1(-3.2,2.385) A4(-2.4,2.385) A9(2.4,2.385) A12(3.2,2.385)
  rect 0.3x1.14 smd: A5(-1.25,2.385) A6(-0.25,2.385) A7(0.25,2.385) A8(1.25,2.385) B5(1.75,2.385) B6(0.75,2.385) B7(-0.75,2.385) B8(-1.75,2.385)
  oval 0.9x2 hole 0.6 slot 1.7 at 90 deg: SHLD(-4.325,1.795) SHLD(4.325,1.795)
  oval 0.9x1.7 hole 0.6 slot 1.4 at 90 deg: SHLD(-4.325,-2.385) SHLD(4.325,-2.385)
  oval 0.9x2 on Top Paste: ""(-4.32,1.795) ""(4.32,1.795)
  oval 0.9x1.7 on Top Paste: ""(-4.32,-2.385) ""(4.32,-2.385)
  silkscreen extent -4.33,-4.48 4.33,0.47, body extent -4.48,-4.98 4.48,2.74, height 3.26
SEGGER_LOGO_S [mm] "Logo 7.82 mm x 3.84 mm, print overlay"
  silkscreen extent -3.91,-1.92 3.91,1.92
Shunt_2.54mm_Vertical [mm]
  body extent -2.51,-1.24 2.51,1.24, height 9
Solderbridge [mil]
  round 1 smd paste-99999: 1(-13.78,0) 2(13.78,0)
  Top Layer region: -7.49,19.36 -15.76,15.74 -21.55,8.8 -23.62,0 -23.62,0 -21.55,-8.79 -15.76,-15.74 -7.49,-19.36 -7.49,-19.36 -6.18,-19.31 -5.02,-18.71 -4.22,-17.68 -3.94,-16.4 -3.94,-16.4 -3.94,16.4 -4.22,17.68 -5.02,18.71 -6.18,19.31 -7.49,19.36
  Top Layer region: 7.49,-19.36 15.76,-15.74 21.55,-8.8 23.62,0 23.62,0 21.55,8.79 15.76,15.74 7.49,19.36 7.49,19.36 6.18,19.31 5.02,18.71 4.22,17.68 3.94,16.4 3.94,16.4 3.94,-16.4 4.22,-17.68 5.02,-18.71 6.18,-19.31 7.49,-19.36
Solderbridge_0.4#1 [mm]
  round 0.2 smd paste-10: 1(-0.312,0) 2(0.312,0)
  Top Layer region: -0.077,-0.553 -0.129,-0.605 -0.205,-0.554 -0.409,-0.351 -0.462,-0.292 -0.521,-0.193 -0.549,-0.099 -0.544,0.122 -0.518,0.193 -0.434,0.33 -0.351,0.411 -0.259,0.469 -0.159,0.556 -0.08,0.565
  Top Layer region: 0.077,0.553 0.203,0.512 0.335,0.424 0.409,0.351 0.462,0.292 0.521,0.193 0.549,0.099 0.544,-0.122 0.518,-0.193 0.434,-0.33 0.351,-0.411 0.152,-0.536 0.077,-0.559
  Top Layer lines w0.152: -0.156,0.557 ccw(c-0.035,0) -0.312,0.498 ccw(c-0.035,0) -0.552,-0.24 ccw(c-0.035,0) -0.312,-0.498 ccw(c-0.035,0) -0.153,-0.558 ; 0.153,0.557 cw(c0.03,0) 0.549,0.237 cw(c0.03,0) 0.6,0 cw(c0.03,0) 0.153,-0.557
Solderbridge_0.4#2 [mm]
  round 0.2 smd paste-10: 1(-0.312,0) 2(0.312,0)
  Top Layer region: 0.077,0.553 0.203,0.512 0.335,0.424 0.409,0.351 0.462,0.292 0.521,0.193 0.549,0.099 0.544,-0.122 0.518,-0.193 0.434,-0.33 0.351,-0.411 0.152,-0.536 0.077,-0.559
  Top Layer region: -0.077,-0.553 -0.129,-0.605 -0.205,-0.554 -0.409,-0.351 -0.462,-0.292 -0.521,-0.193 -0.549,-0.099 -0.544,0.122 -0.518,0.193 -0.434,0.33 -0.351,0.411 -0.259,0.469 -0.159,0.556 -0.08,0.565
  Top Layer lines w0.152: -0.153,-0.558 cw(c-0.035,0) -0.312,-0.498 cw(c-0.035,0) -0.312,0.498 cw(c-0.035,0) -0.156,0.557 ; 0.153,-0.557 ccw(c0.03,0) 0.549,-0.237 ccw(c0.03,0) 0.153,0.557
Solderbridge_Shorted [mil]
  round 1 smd paste-99999: 1(-13.78,0) 2(13.78,0)
  Top Layer region: -4.92,3.94 -4.92,-3.94 4.92,-3.94 4.92,3.94
  Top Layer region: -7.49,19.36 -15.76,15.74 -21.55,8.8 -23.62,0 -23.62,0 -21.55,-8.79 -15.76,-15.74 -7.49,-19.36 -7.49,-19.36 -6.18,-19.31 -5.02,-18.71 -4.22,-17.68 -3.94,-16.4 -3.94,-16.4 -3.94,16.4 -4.22,17.68 -5.02,18.71 -6.18,19.31 -7.49,19.36
  Top Layer region: 7.49,-19.36 15.76,-15.74 21.55,-8.8 23.62,0 23.62,0 21.55,8.79 15.76,15.74 7.49,19.36 7.49,19.36 6.18,19.31 5.02,18.71 4.22,17.68 3.94,16.4 3.94,16.4 3.94,-16.4 4.22,-17.68 5.02,-18.71 6.18,-19.31 7.49,-19.36
Solderbridge_SHORTED_0.4 [mm]
  round 0.2 smd paste-10: 1(-0.312,0) 2(0.312,0)
  Top Layer region: 0.077,0.553 0.203,0.512 0.335,0.424 0.409,0.351 0.462,0.292 0.521,0.193 0.549,0.099 0.544,-0.122 0.518,-0.193 0.434,-0.33 0.351,-0.411 0.152,-0.536 0.077,-0.559
  Top Layer region: -0.077,-0.553 -0.129,-0.605 -0.205,-0.554 -0.409,-0.351 -0.462,-0.292 -0.521,-0.193 -0.549,-0.099 -0.544,0.122 -0.518,0.193 -0.434,0.33 -0.351,0.411 -0.259,0.469 -0.159,0.556 -0.08,0.565
  Top Layer lines w0.152: 0.153,0.557 cw(c0.03,0) 0.153,-0.557 ; -0.153,-0.558 cw(c-0.035,0) -0.156,0.557
  Top Layer lines w0.203: 0.363,0 -0.312,0
SON50P100X50-6N [mm] "SON, 6-Leads, Body 1,45x1,00mm, Pitch 0,50mm, IPC Medium Density"
  rect 0.7x0.2 smd: 1(-0.465,0.5) 2(-0.465,0) 3(-0.465,-0.5) 4(0.465,-0.5) 5(0.465,0) 6(0.465,0.5)
  silkscreen extent -0.95,-0.88 0.53,0.92, body extent -0.53,-0.75 0.53,0.75, height 0.5
SOT95P280X145-5N [mm] "SOT23, 5-Leads, Body 2,90x2,80mm, Pitch 0,95mm, IPC Medium Density"
  rect 1x0.6 smd: 1(-1.35,0.95) 2(-1.35,0) 3(-1.35,-0.95) 4(1.35,-0.95) 5(1.35,0.95)
  silkscreen extent -1.47,-1.5 0.45,1.92, body extent -1.5,-1.55 1.5,1.55, height 1.45
Switch-PB-6.2x6.3mm-SMD [mm] "6.2×6.5mm TACT Switch, without ground connector"
  rect 2.75x1.4 smd: 1(-3.375,2) 1(3.375,2) 2(-3.375,-2) 2(3.375,-2)
  silkscreen extent -3,-3 3,3, body extent -3.6,-3.1 3.6,3.1, height 2.5
TC2050-IDC-NLFP [mil]
  round 39 hole 39 unplated mask+0.79: 0(-150,0) 0(150,-40) 0(150,40)
  round 31 smd paste-196.85: 1(-100,-25) 2(-50,-25) 3(0,-25) 4(50,-25) 5(100,-25) 6(100,25) 7(50,25) 8(0,25) 9(-50,25) 10(-100,25)
  Top Layer pour cut-out: -100,25 -100,-25 100,-25 100,25
TP_SMD_D1.5mm#1 [mm] "Test point - pad 1.5mm"
  round 1.5 smd paste-5: 1(0,0)
  body extent -0.75,-0.75 0.75,0.75, height 0.05
TP_SMD_D1.5mm#2 [mm] "Test point - pad 1.5mm"
  round 1.5 smd paste-5: 1(0,0.01)
  body extent -0.75,-0.75 0.75,0.75, height 0.05
TSSOP6 [mm] "TSSOP6 (SOT-363)"
  rect 0.6x0.6 smd: 1(-0.75,-0.9) 3(0.75,-0.9) 4(0.75,0.9) 6(-0.75,0.9)
  rect 0.4x0.6 smd: 2(0,-0.9) 5(0,0.9)
  silkscreen extent -1.47,-1.07 1,0.45, body extent -1,-1.05 1,1.05, height 0.93
WEEE_3x4.5mm [mm]
  silkscreen extent -1.47,-2.7 1.47,1.71
XQFN40P180X260X50-16N [mm] "QFN, 16-Leads, Body 1.80x2.60mm, Pitch 0.40mm, IPC Medium Density"
  rect 0.65x0.22 smd paste-0.02 mask+0.05: 1(-0.725,0.6)
  rect 0.55x0.22 smd paste-0.02 mask+0.03: 2(-0.775,0.2) 3(-0.775,-0.2) 4(-0.775,-0.6) 9(0.775,-0.6) 10(0.775,-0.2) 11(0.775,0.2) 12(0.775,0.6)
  rect 0.22x0.55 smd paste-0.02 mask+0.03: 5(-0.6,-1.175) 6(-0.2,-1.175) 7(0.2,-1.175) 8(0.6,-1.175) 13(0.6,1.175) 14(0.2,1.175) 15(-0.2,1.175) 16(-0.6,1.175)
  silkscreen extent -1.36,-1.37 0.97,1.37, body extent -0.9,-1.3 0.9,1.3, height 0.55
XTAL_2012 [mm] "XTAL SMD 2.0 x 1.2 mm"
  rect 0.75x1.4 smd: 1(-0.725,0) 2(0.725,0)
  silkscreen extent -0.24,-0.6 0.24,0.6, body extent -1,-0.61 1,0.61, height 0.6

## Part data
C1: library part C0201-2µ2-2.5V-X6T-GRM033D80E225ME47D, "Capacitor, Ceramic, 2.2µF 2.5V X6T 0201,±20%", Manufacturer=Murata, Manufacturer Part Number=GRM033R61A225KE47, Part number IPS=N.A., Part number NEMS=100200527, Supplier Part Number 1=81-GRM033D80E225ME7D
C2 C13 C16: library part C0201-N.C., "Not mounted", Manufacturer=N.A., Part number NEMS=100200001
C3: library part C0402-10µF-6.3V-X6S, "Capacitor, X6S, ±20%, 6.3V", Manufacturer=N.A., Part number NEMS=100200478
C5: library part C0201-10n-6.3V-X7R, "Capacitor, X7R, 6.3V", Manufacturer=Murata, Manufacturer Part Number=GRM033R70J103KA01D, Part number IPS=N.A., Part number NEMS=100200407, Supplier Part Number 1=490-1262-1-ND
C6: library part C0201-0p4-25V-C0G-GJM0335C1ER40WB01D, "Capacitor, C0G, ±0.05pF, 25V", Manufacturer=Murata, Part number IPS=N.A., Part number NEMS=100200706, Supplier Part Number 1=490-8074-2-ND
C9: library part C0201-1.5p-25V-NP0-GJM0335C1E1R5WB01, "Capacitor, NP0, ±0.05pF, 25V, High Q", Manufacturer=Murata, Part number IPS=N.A., Part number NEMS=100200477, Supplier Part Number 1=490-11176-2-ND
C10: library part C0201-100n-10V-X7R, "Capacitor, X7R, ±10%", Manufacturer=N.A., Part number NEMS=100200469
C11: library part C0201-1p0-25V-COG-GJM0335C1E1R0WB01, "CAP CER 1.0PF 25V C0G/NP0 0201", Manufacturer=Murata, Part number IPS=N.A., Part number NEMS=100200676, Supplier Part Number 1=490-10677-1-ND
C12: library part C0201-2µ2, "Capacitor, X5R, ±20%", Manufacturer=N.A., Part number NEMS=100200375, Supplier Part Number 1=1276-6829-1-ND
C14 C15 C18 C20 C22 C25 C29 C34 C35 C36 C37 C44 C46 C48 C49 C52 C53 C55 C56 C57 C62 C63 C64 C69 C70 C72 C73 C74 C75 C76 C77 C78 C79 C80 C81 C83: library part C0201-100n, "Capacitor, X5R, ±10%", Manufacturer=N.A., Part number IPS="00000001248, 00000002505", Part number NEMS=100200078, Part number Norautron=262071862
C23: library part C0402-2µ2-10V, "Capacitor, X5R, ±10%", Manufacturer=N.A., Part number NEMS=100200376, Supplier Part Number 1=490-10451-1-ND
C24 C26 C27: library part C0603-10µ-10V-X7T-GRM188D71A106MA73, "Capacitor, X7T, ±20%, 10V", Manufacturer=Murata, Manufacturer Part Number=GRM188D71A106MA73, Part number IPS=00000004696, Part number NEMS=100200414, Part number Norautron=N.A., Supplier Part Number 1=490-7200-1-ND
C28 C31 C32 C39 C45 C50 C51 C68 C82 C84: library part C0402-1µ0-6.3V-X5R-10%, "Capacitor, X5R, ±10%, 6.3V", Manufacturer=N.A., Part number NEMS=100200498, Part number Norautron=26207137
C30 C67: library part C0201-10n, "Capacitor, X7R, ±10%", Manufacturer=N.A., Part number IPS=00000003480, Part number NEMS=100200067, Part number Norautron=26621779
C33: library part C0201-2n2, "Capacitor, X7R, ±10%, 10V", Manufacturer=N.A., Part number IPS=00000001778, Part number NEMS=100200060, Part number Norautron=26470002
C38: library part C0201-1.4p-25V-GJM0335C1E1R4WB01D, "Capacitor, C0G, ±0.05pF, 25V", Manufacturer=Murata, Manufacturer Part Number=GJM0335C1E1R4WB01D, Part number IPS=N.A., Part number NEMS=100200553, Supplier Part Number 1=490-GJM0335C1E1R4WB01DTR-ND
C40: library part C0603-2µ2-6.3V-X7R, "Capacitor, X7R, ±10%, 6.3V", Manufacturer=N.A., Part number NEMS=100200272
